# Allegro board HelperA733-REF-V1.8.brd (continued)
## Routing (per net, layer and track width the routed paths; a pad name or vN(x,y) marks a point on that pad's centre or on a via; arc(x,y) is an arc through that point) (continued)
5V-IN: length 7.6
  TOP w0.889: U1.164 57.21,41.7 57.21,42.7 U1.163
  TOP w2.032: 55.11,40.2 57.21,42.3
12V-IN: length 9.5
  TOP w0.152: R157.1 R238.2 24.4,14.4 24.47,14.33 24.47,11.77 v1(24.51,11.77)
  BOTTOM w0.152: v1(19.41,11.8) 24.45,11.8 24.47,11.77 v1(24.51,11.77)
AVCC: length 117.6
  TOP w0.152: J16.11 52.61,7.4 53.41,8.2 D58.7 D58.4 53.41,13.64 54.01,14.24 54.01,16.9 57.71,20.6 57.71,22.6 58.81,23.7 U1.182 59.21,23.7 67.41,31.9 67.41,66.83 v1(67.38,66.83) ; v1(41.01,89.2) R61.1
  BOTTOM w0.152: v1(67.38,66.83) 66.91,67.3 42.43,67.3 40.81,68.92 40.81,76.91 40.81,76.91 40.81,89 v1(41.01,89.2)
AVDD: length 47.3
  TOP w0.152: v1(140.71,77.5) 140.61,77.5 138.29,75.18 R30.1 ; v1(138.71,83.4) 138.77,83.4
  TOP w0.3: R39.2 v1(139.01,93.2)
  TOP w0.305: J4.29 143.91,58.9
  TOP w0.5: 143.91,58.9 145.61,58.9 147.11,60.4 147.11,71.1 v1(145.41,72.8)
  TOP w0.508: 140.7,87.43 140.7,84.11 140.15,83.55 138.92,83.55 D26.1
  BOTTOM w0.152: v1(139.01,93.2) v1(139.01,89.1)
  BOTTOM w0.56: v1(145.41,72.8) v1(140.71,77.5) 138.1,80.11 138.1,83.09 138.41,83.4 v1(138.71,83.4)
AVDD10: length 54.7
  TOP w0.203: U10.21 112.91,72.23 112.68,72 ; 118.06,76.33 118.03,76.3 U10.38 ; 113.71,78.62 U10.8 113.71,77.24 113.84,77.12 115.59,77.12 115.71,77.24 U10.3 115.71,78.53
  TOP w0.254: v1(121.12,79.25) 121.12,78.98 120.89,78.75 120.09,78.75 119.56,78.22 119.59,78.22 CE1.2 118.99,78.2 118.26,77.47 118.26,76.54 118.06,76.33 ; v1(116.57,80.81) 116.57,80.35 116.19,79.97 CE5.2 115.71,79.88 115.71,78.53 ; 113.71,78.62 113.71,79.78 CE4.2 ; 112.68,72 112.17,71.49 110.54,71.49 109.79,70.74 109.02,70.74 CE2.2
  TOP w0.4: L6.2 122.61,71.1 121.71,72 v1(121.41,72)
  TOP w0.5: 123.79,69.86 CE3.2 ; 123.79,69.86 CE6.2 ; 123.79,69.86 123.4,69.86 123.35,69.8 L6.2
  BOTTOM w0.3: v1(121.12,79.25) 121.12,79.17 ; 121.12,79.17 119.49,80.81 v1(116.57,80.81) 112.92,80.81 110.81,78.7 109.95,78.7 108.61,77.36 108.61,70.86 v1(108.87,70.6) ; 121.12,79.17 121.12,72.19 121.31,72 v1(121.41,72)
AVDD33: length 60.1
  TOP w0.152: 118.96,80.15 v1(118.93,80.18)
  TOP w0.203: U10.40 117.26,77.4
  TOP w0.254: v1(107.93,74.49) 107.93,74.5 108.59,74.5 RE3.1 ; RE1.1 120.44,72 v1(120.44,72.53) 120.44,73.1 R84.1 ; v1(109.31,68.58) 109.51,68.78 109.51,69.18 ; v1(112.8,68.57) 112.8,69.18 112.81,69.18 ; v1(110.09,78.01) 109.44,78.01 CE8.2 ; RE2.1 108.59,77.3 108.7,77.41 109.09,77.41 109.38,77.7 109.38,78.1 ; R85.2 108.59,82.77 108.75,82.61 109.01,82.61 109.24,82.38 FB2.2 ; 111.71,69.18 111.71,69.18 v1(111.71,68.58) ; 117.26,77.4 117.26,77.5 118.7,78.93 118.7,79.89 118.96,80.15 119.21,80.4 CE9.2 ; 116.1,72.75 116.1,71.69 116.01,71.6 115.73,71.6 115.73,72.38 115.71,72.4 U10.28 ; v1(110.51,68.58) 110.61,68.67 110.61,69.18
  TOP w0.3: 118.27,70.07 117.76,70.58 116.43,70.58 115.91,71.1 115.91,71.5 116.01,71.6 ; 118.27,70.07 CE10.2 CE12.2 ; 118.27,70.07 v1(118.85,70.07)
  BOTTOM w0.254: v1(112.8,68.57) 111.72,68.57 v1(111.71,68.58) 110.59,68.58 v1(110.51,68.58) 110.51,68.58 v1(109.31,68.58) 108.23,68.58 107.91,68.9 107.91,74.4 v1(107.93,74.49) 107.91,74.49 107.91,77.97 109.48,79.54 v1(110.09,79.54)
  BOTTOM w0.3: v1(110.09,78.01) 110.87,78.01 113.03,80.17 118.74,80.17 ; 118.74,80.17 118.75,80.18 v1(118.93,80.18) ; 118.74,80.17 119.54,80.17 120.44,79.28 120.44,72.63 120.39,72.58 v1(120.44,72.53) 119.54,72.53 118.85,71.84 v1(118.85,70.07)
  vias: v1(110.09,81.68) v1(110.09,80.96) v1(110.09,80.25) v1(110.09,80.25)
AVDD-CSI: length 26.2
  TOP w0.254: R16.1 92.05,12.93 v1(92.05,13.61) ; v1(90.53,13.61) 90.53,12.93 R15.1
  TOP w0.305: CON1.38 89.96,6.85 90.32,7.21 90.89,7.21
  TOP w0.508: 90.89,7.21 92.42,7.21 v1(92.44,7.23) ; U1.36 96.01,15.1 96.92,14.19 v1(96.92,12.94) 96.92,12.32 96.67,12.08 CP3.1 D11.2 96.62,10.66 96.92,10.36 96.92,7.31 v1(96.91,7.31)
  BOTTOM w0.254: v1(96.92,12.94) 92.71,12.94 v1(92.05,13.61) 92.05,13.61 v1(90.53,13.61)
  BOTTOM w0.508: v1(96.91,7.31) 96.91,7.23 v1(92.44,7.23)
DVDD-CSI: length 17.8
  TOP w0.305: CON1.37 89.66,3.63 90.01,3.98
  TOP w0.508: U1.35 95.01,15.14 95.01,14.4 95.31,14.1 95.31,12.36 95.03,12.08 CP2.1 D10.2 95.02,10.66 95.17,10.5 95.17,6.88 94.01,5.72 91.63,5.72 90.02,4.12 90.01,3.98
GND: length 1284.1
  TOP w0.127: v1(68.12,88.1) 68.89,87.33 UA1.41
  TOP w0.152: v1(13.21,37.6) 30.11,37.6 32.41,39.9 32.41,39.92 55.21,62.72 v1(55.21,64.8) ; v1(108.01,6.7) 108.01,6.6 106.13,8.49 106.13,11.51
  TOP w0.203: 119.24,68.4 124.83,68.4 126.23,69.8 v1(126.23,70.37) ; 119.24,68.4 118.85,68.79 v1(118.85,69.12) ; 119.24,68.4 119.24,68.34 117.79,66.89 117.34,66.89 115.65,65.19 104.67,65.19 104.04,65.19 v1(100.08,61.23) ; 44.95,80.36 44.95,77.67 46.26,76.36 46.26,76.09 ; 44.95,80.36 45.07,80.36 ; 44.95,80.36 43.18,80.36 42.4,79.58 ; 46.26,75.82 J12.45
  TOP w0.254: 19.19,26.4 19.19,26.67 ; 140.84,91.52 140.57,91.52 ; 63.93,94.28 63.66,94.28 ; 143.73,63.9 143.46,63.9 ; 85.16,6.97 85.16,6.85 ; 138.19,80.9 137.92,80.9 ; 25.11,76.75 25.11,76.48 ; 87.21,40.97 87.21,40.7 ; 28.69,81.42 28.69,81.15 ; 115.24,14.52 115.24,14.25 ; 97.71,9.17 97.71,9.44 ; 37.71,92.34 37.71,92.08 ; 75.4,99.65 75.66,99.65 ; 81.11,97.41 81.11,97.53 ; v1(43.86,92.41) 43.87,92.4 43.87,91.59 43.77,91.49 43.77,91.03 43.68,90.94 D48.1 ; 5.65,83.38 5.65,83.65 ; 97.36,86.9 97.36,87.16 ; 141.41,93.36 141.41,93.62 ; 136.39,71.38 136.39,71.65 ; 76.12,98.93 76.12,99.2 ; 37.26,74.01 37.26,74.27 ; 52.2,97.85 52.2,97.58 ; 14.58,63.12 14.31,63.12 ; 69.09,97.52 69.09,97.25 ; 76.84,99.65 76.58,99.65 ; 125.15,69.3 124.89,69.3 ; 102.46,86.79 102.73,86.79 ; 141.69,69.9 141.7,69.9 ; 75.05,87.2 74.79,87.2 ; 73.44,4.2 73.71,4.2 ; 75.48,2.93 75.21,2.93 ; 45.91,11.39 45.91,11.13 ; 137.65,78 137.65,78.27 ; 22.87,86.48 22.87,86.75 ; 34.16,72.63 34.16,72.9 ; 114.71,73.53 114.71,73.8 ; 46.53,90.94 46.26,90.94 ; 80.51,88.78 80.51,89.05 ; 146.24,16.2 146.51,16.2 ; 143.76,77.08 143.76,77.35 ; 87.21,38.43 87.21,38.7 ; 18.97,86.48 18.97,86.75 ; 11.51,76.75 11.51,76.48 ; 77.4,90.35 77.4,90.08 ; 26.59,15.28 26.86,15.28 ; 75.48,5.47 75.21,5.47 ; 18.97,87.52 18.97,87.25 ; 35.76,76.09 35.76,75.82 ; 148.78,16.2 148.51,16.2 ; 136.91,78.9 137.18,78.9 ; 27.95,80.9 27.69,80.9 ; 136.07,8.98 136.07,9.25 ; 141.69,59.4 141.71,59.4 ; 47.69,77.58 47.69,77.85 ; 75.48,4.2 75.21,4.2 ; 29.59,53.9 29.86,53.9 ; 54.22,91.17 54.22,91.44 ; 139.94,92.25 139.94,91.99 ; 144.35,82.2 144.35,82.47 ; 129.65,10.02 129.65,9.75 ; 44.64,88.3 44.65,88.29 v1(44.65,88.28) ; 136.71,80.9 136.98,80.9 ; 31.06,57.3 30.8,57.3 ; 26.31,49.64 26.31,49.91 ; 9.51,67.55 9.51,67.28 ; 49.07,91.7 49.34,91.7 ; 75.33,96.03 75.06,96.03 ; 141.41,91.14 141.41,90.88 ; 13.31,50.74 13.31,50.47 ; 79.16,94.69 79.43,94.69 ; 49.91,11.39 49.91,11.13 ; 74.46,3.4 74.46,3.13 ; 77.39,90.48 77.39,90.75 ; 61.89,94.28 62.16,94.28 ; 140.01,92.74 140.01,93.01 ; 140.91,79.16 140.91,79.43 ; 50.44,77.58 50.44,77.85 ; 88.65,87.5 88.39,87.5 ; 129.37,3.3 129.64,3.3 ; 145.09,79.1 144.82,79.1 ; 65.71,81.06 65.71,81.33 ; 68.06,93.21 68.33,93.21 ; 29.59,55.6 29.86,55.6 ; 30.33,40.4 30.33,40.67 ; 136.09,83.33 136.09,83.07 ; 62.41,93.76 62.41,94.03 ; 74.81,96.54 74.81,96.28 ; 77.39,91.52 77.39,91.25 ; 135.31,2.03 135.31,2.3 ; v1(43.2,88.21) 43.2,87.99 44.84,86.35 v1(51.44,86.35) ; 120.95,80.4 120.69,80.4 ; 129.65,8.98 129.65,9.25 ; 56.06,92.57 55.79,92.57 ; 8.37,84.42 8.37,84.15 ; 88.14,85.48 88.14,85.75 ; 1.31,63.74 1.31,63.47 ; 56.22,97.85 56.22,97.58 ; 5.65,84.42 5.65,84.15 ; 49.2,92.45 49.2,92.72 ; 77.8,3.34 78.06,3.34 ; 74.46,2.46 74.46,2.73 ; 14.24,41 13.97,41 ; 91.33,3.34 91.06,3.34 ; 1.31,50.74 1.31,50.47 ; 14.35,28.23 14.35,27.97 ; 12.04,50.12 12.31,50.12 ; 1.18,83.9 1.45,83.9 ; 76.27,100.8 76.54,100.8 ; 6.32,38.65 6.59,38.65 ; 88.67,90.5 88.4,90.5 ; 141.93,93.88 141.66,93.88 ; 52.76,76.09 52.76,75.82 ; 25.79,53.93 26.06,53.93 ; 85.94,39.7 86.21,39.7 ; 2.58,50.12 2.31,50.12 ; 115.24,13.48 115.24,13.75 ; 137.67,60.1 137.94,60.1 ; 112.94,75.3 113.21,75.3 ; 31.06,41.3 30.8,41.3 ; 84.81,94.77 84.81,94.79 ; 144.35,80 144.35,79.73 ; 123.88,9.5 124.15,9.5 ; 32.58,74.88 32.32,74.88 ; 13.64,44.52 13.64,44.4 ; 56.79,97.33 56.52,97.33 ; 108.07,80.2 108.34,80.2 ; 19.44,59.6 19.18,59.6 ; 131.25,3.3 130.99,3.3 ; 43.26,74.01 43.26,74.27 ; 8.37,83.38 8.37,83.46 ; 144.65,82 144.65,81.73 ; 96.11,9.17 96.11,9.44 ; 94.51,9.17 94.51,9.44 ; 63.93,97.03 63.66,97.03 ; 77.4,89.05 77.4,89.32 ; 31.06,46.4 30.8,46.4 ; 26.31,54.44 26.31,54.18 ; 125.15,70.3 124.89,70.3 ; 133.65,22.92 133.65,22.65 ; 37.31,61.66 37.31,61.93 ; 130.31,2.03 130.31,2.3 ; 45.13,90.94 44.86,90.94 ; 38.81,90.24 38.81,89.97 ; 138.19,76.9 137.92,76.9 ; 74.46,4.67 74.46,4.4 ; 15.11,67.55 15.11,67.28 ; 109.23,90.95 108.96,90.95 ; 143.73,60.9 143.46,60.9 ; 101.76,86.9 101.76,87.16 ; 6.32,34.65 6.59,34.65 ; 92.59,12.93 92.86,12.93 ; 78.21,2.5 78.21,2.76 ; 27.63,15.28 27.36,15.28 ; 18.31,67.55 18.31,67.28 ; 108.41,68.76 108.41,68.8 ; 108.36,91.92 108.36,91.65 ; 31.06,55.6 30.8,55.6 ; 138.19,61.62 138.19,61.35 ; 20.05,87.52 20.05,87.25 ; 40.26,76.09 40.26,75.82 ; 123.58,55.3 123.85,55.3 ; 62.41,97.54 62.41,97.28 ; 26.96,50.29 26.69,50.29 ; 22.71,76.75 22.71,76.48 ; 31.16,73.01 31.16,73.27 ; 8.94,83.9 8.67,83.9 ; 29.59,57.3 29.86,57.3 ; 51.67,26.08 51.67,26.35 ; 1.75,84.42 1.75,84.15 ; 16.05,86.48 16.05,86.75 ; 9.51,65 9.51,65.27 ; 33.29,74.27 33.56,74.27 ; 100.49,10.66 100.76,10.66 ; 125.31,2.03 125.31,2.3 ; 141.71,17.13 141.71,16.86 ; 136.64,9.5 136.37,9.5 ; 144.35,84 144.35,83.73 ; 52.76,74.01 52.76,74.1 ; 16.49,42.38 16.76,42.38 ; 116.48,75.3 116.21,75.3 ; 125.67,58.6 125.4,58.6 ; 74.46,5.94 74.46,5.67 ; 141.93,90.62 141.66,90.62 ; 137.65,79.8 137.65,79.53 ; 46.26,74.01 46.26,74.06 ; 94.51,13.44 94.51,13.18 ; 23.95,87.52 23.95,87.25 ; 108.07,78 108.34,78 ; 56.22,96.81 56.22,97.07 ; 16.05,87.52 16.05,87.25 ; 130.07,101.4 130.34,101.4 ; 53.26,76.09 53.26,75.82 ; 141.43,79.68 141.16,79.68 ; 108.07,79.1 108.34,79.1 ; 124.15,55.82 124.15,55.55 ; 22.87,87.52 22.87,87.25 ; 88.14,88.58 88.14,88.85 ; 143.61,83.1 143.88,83.1 ; 63.41,97.54 63.41,97.28 ; 88.14,88.02 88.14,87.75 ; 17.99,56.08 17.99,56.35 ; 43.26,76.09 43.26,75.82 ; 141.69,62.4 141.96,62.4 ; 36.61,90.24 36.61,89.97 ; 25.89,45.88 25.89,46.15 ; 23.74,12.88 23.74,13.1 ; 137.67,59.1 137.94,59.1 ; 65.41,93.04 65.41,92.78 ; 52.2,96.81 52.2,97.07 ; 141.69,65.4 141.96,65.4 ; 81.63,95.44 81.36,95.44 ; 88.14,86.52 88.14,86.25 ; 25.31,14.76 25.31,15.03 ; 36.61,90.37 36.61,90.64 ; 88.14,91.38 88.14,91.65 ; 131.46,88.59 131.19,88.59 ; 26.83,53.93 26.56,53.93 ; 93.11,9.17 93.11,9.44 ; 29.59,50.6 29.86,50.6 ; 51.63,97.33 51.9,97.33 ; 41.76,74.01 41.76,74.27 ; 100.66,86.9 100.66,87.16 ; 93.73,100.55 93.46,100.55 ; 8,41.15 7.74,41.15 ; 69.59,98.04 69.86,98.04 ; 26.31,45.34 26.31,45.08 ; 18.88,66.28 18.62,66.28 ; 125.31,4.57 125.31,4.3 ; 76.12,100.38 76.12,100.11 ; 94.78,90.95 94.51,90.95 ; 45.37,80.8 45.64,80.8 ; 87.84,11.39 87.84,11.13 ; 88.02,91.15 88.02,90.88 ; 1.31,49.5 1.31,49.77 ; 130.15,95.22 130.15,94.95 ; 53.91,11.39 53.91,11.13 ; 141.69,63.9 141.74,63.9 ; 62.47,88.4 62.74,88.4 ; 91.99,100.55 92.26,100.55 ; 78.09,86.5 78.36,86.5 ; 39.33,89.72 39.06,89.72 ; 11.91,67.55 11.91,67.28 ; 49.2,93.75 49.2,93.48 ; 54.86,75.92 54.86,75.65 ; 88.02,85.15 88.02,84.88 ; 90.91,9.37 90.91,9.41 ; 139.05,94.1 138.79,94.1 ; 41.76,76.09 41.76,75.82 ; 93.76,89.93 93.76,90.2 ; 133.59,78.47 133.86,78.47 ; 79.76,5.23 79.76,5.5 ; 31.06,44.7 30.8,44.7 ; 80.59,95.44 80.86,95.44 ; 24.51,23.38 24.25,23.38 ; 138.39,78.9 138.12,78.9 ; 130.59,100.88 130.59,101.15 ; 34.16,75.92 34.16,75.65 ; 46.01,90.37 46.01,90.64 ; 29.74,74.88 30,74.88 ; 26.74,55.28 26.74,55.55 ; 62.47,87.3 62.74,87.3 ; 143.91,81.1 144.18,81.1 ; 124.64,68.78 124.64,69.05 ; 48.55,93.1 48.82,93.1 ; 113.51,81.76 113.51,81.49 ; 144.28,77.6 144.01,77.6 ; 82.69,95.34 82.96,95.34 ; 1.75,83.38 1.75,83.65 ; 147.51,15.26 147.51,15.53 ; 144.65,80.2 144.65,80.47 ; 126.25,3.3 125.99,3.3 ; 49.59,88.78 49.59,89.05 ; 13.31,62.5 13.31,62.77 ; 141.69,66.9 141.71,66.9 ; 88.65,91.9 88.39,91.9 ; 75.49,95.18 75.76,95.18 ; 136.71,76.9 136.98,76.9 ; 138.54,94.62 138.54,94.35 ; 137.58,69.83 137.61,69.83 ; 134.37,3.3 134.64,3.3 ; 93.11,13.44 93.11,13.18 ; 61.89,97.03 62.16,97.03 ; 129.08,9.5 129.35,9.5 ; 49.26,76.09 49.26,75.82 ; 92.74,90.95 93.01,90.95 ; 35.81,62.32 35.81,62.05 ; 8.31,76.75 8.31,76.48 ; 88.67,84.5 88.4,84.5 ; 31.06,53.9 30.8,53.9 ; 75.05,88.2 74.79,88.2 ; 86.31,43.97 86.31,43.7 ; 21.75,18.7 21.49,18.7 ; 86.31,41.43 86.31,41.7 ; 135.87,71.9 136.14,71.9 ; 13.83,27.72 14.1,27.72 ; 137.45,80 137.45,80.27 ; 62.6,84.65 62.6,84.38 ; 88.65,86 88.39,86 ; 125.64,63.3 125.38,63.3 ; 31.06,52.3 30.8,52.3 ; 30.33,58.2 30.33,57.94 ; 1.86,76.74 1.86,76.48 ; 124.45,8.98 124.45,9.25 ; 124.37,3.3 124.64,3.3 ; 138.04,91.86 138.04,91.59 ; 53.61,86.56 53.61,86.83 ; 20.05,86.48 20.05,86.75 ; 53.09,87.08 53.36,87.08 ; 52.24,26.6 51.97,26.6 ; 34.41,88.36 34.41,88.62 ; 1.86,73.01 1.86,73.27 ; 17.01,41.86 17.01,42.12 ; 130.31,4.57 130.31,4.3 ; 66.41,93.04 66.41,92.78 ; 144.35,78.2 144.35,78.47 ; 145.39,81.1 145.12,81.1 ; 54.86,72.63 54.86,72.9 ; 57.91,11.39 57.91,11.13 ; 25.37,46.4 25.64,46.4 ; 40.26,74.01 40.26,74.27 ; 76.79,101.32 76.79,101.05 ; 31.16,76.74 31.16,76.48 ; 35.26,74.01 35.26,74.27 ; 31.06,50.6 30.8,50.6 ; 88.14,89.62 88.14,89.35 ; 107.49,100.55 107.76,100.55 ; 92.59,9.74 92.86,9.74 ; 1.31,62.5 1.31,62.77 ; 13.31,63.74 13.31,63.47 ; 38.76,76.09 38.76,75.82 ; 139.03,91.52 139.3,91.52 ; 45.49,90.94 45.76,90.94 ; 25.79,44.83 26.06,44.83 ; 88.02,89.85 88.02,90.12 ; 103.11,86.14 103.11,86.41 ; 88.65,89.1 88.39,89.1 ; 135.36,82.61 135.63,82.61 ; 88.02,83.85 88.02,84.12 ; 87.58,42.7 87.31,42.7 ; 17.11,76.75 17.11,76.48 ; 135.31,4.57 135.31,4.3 ; 92.86,99.18 92.86,99.45 ; 32.79,88.88 33.06,88.88 ; 80.46,94.69 80.19,94.69 ; 49.59,91.18 49.59,91.45 ; 33.31,88.36 33.31,88.62 ; 19.93,27.3 19.66,27.3 ; 27.11,67.55 27.11,67.28 ; 130.81,87.94 130.81,88.21 ; 21.05,11.78 21.05,11.51 ; 54.13,87.08 53.86,87.08 ; 35.26,76.09 35.26,75.82 ; 123.48,66.7 123.75,66.7 ; 46.26,76.09 46.26,75.82 ; 137.39,91.21 137.66,91.21 ; 25.81,50.29 25.93,50.29 ; 18.46,27.3 18.72,27.3 ; 63.41,93.76 63.41,94.03 ; 131.46,96.69 131.19,96.69 ; 37.26,76.09 37.26,75.82 ; 137.67,58.1 137.94,58.1 ; 138.68,91.21 138.42,91.21 ; 4.57,84.42 4.57,84.15 ; 138.15,65.88 138.15,66.15 ; 137.58,66.4 137.85,66.4 ; 30.33,49.7 30.33,49.97 ; 93.76,91.97 93.76,91.7 ; 36.71,61.58 36.45,61.58 ; 17.47,56.6 17.74,56.6 ; 73.33,98.04 73.06,98.04 ; 108.36,99.18 108.36,99.45 ; 49.59,92.22 49.59,91.95 ; 87.26,2.03 87.26,2.08 ; 38.76,74.01 38.76,74.27 ; 108.36,101.92 108.36,101.65 ; 101.01,11.23 101.01,10.96 ; 23.95,86.48 23.95,86.75 ; 130.16,96.69 130.43,96.69 ; 112.86,81.11 113.13,81.11 ; 35.76,74.01 35.76,74.27 ; 145.09,83.1 144.82,83.1 ; 92.86,101.92 92.86,101.65 ; 52.38,92.57 52.64,92.57 ; 35.81,60.85 35.81,61.11 ; 14.11,79.98 14.11,80.25 ; 81.94,11.39 81.94,11.13 ; 53.76,76.09 53.76,75.82 ; 27.44,81.42 27.44,81.15 ; 140.66,93.39 140.39,93.39 ; 17.47,57.6 17.74,57.6 ; 21.56,11.26 21.3,11.26 ; 124.03,64.88 124.03,65.14 ; 147.51,17.14 147.51,16.88 ; 81.11,94.87 81.11,95.14 ; 23.03,27.73 22.76,27.73 ; 73.44,2.93 73.71,2.93 ; 140.39,79.68 140.66,79.68 ; 137.45,77.8 137.45,77.53 ; 17.53,42.38 17.26,42.38 ; 29.59,52.3 29.86,52.3 ; 96.11,13.44 96.11,13.18 ; 26.83,44.83 26.56,44.83 ; 54.22,93.96 54.22,93.7 ; 137.67,61.1 137.94,61.1 ; 12.04,63.12 12.31,63.12 ; 88.48,39.7 88.21,39.7 ; 79.81,94.04 79.81,94.31 ; 115.75,14 115.49,14 ; 46,25.18 46,24.91 ; 97.58,75.7 97.31,75.7 ; 22.71,23.38 22.98,23.38 ; 113.91,68.66 113.91,68.93 ; 38.31,61.66 38.31,61.93 ; 15.48,87 15.75,87 ; 139.94,90.78 139.94,91.05 ; 73.44,5.47 73.71,5.47 ; 51.51,77.56 51.51,77.83 ; 140.89,90.62 141.16,90.62 ; 109.23,100.55 108.96,100.55 ; 108.36,89.98 108.36,90.25 ; 98.46,86.9 98.46,87.16 ; 85.04,42.7 85.31,42.7 ; 55.73,74.27 55.46,74.27 ; 107.89,69.28 108.16,69.28 ; 136.81,82.61 136.55,82.61 ; 134.11,77.96 134.11,78.22 ; 84.88,11.42 84.88,11.15 ; 130.81,96.04 130.81,96.31 ; 74.46,3.73 74.46,4 ; 136.55,10.6 136.29,10.6 ; 27.11,14.76 27.11,15.03 ; 108.07,75.8 108.34,75.8 ; 49.07,89.3 49.34,89.3 ; 103.76,86.79 103.49,86.79 ; 28.17,80.9 28.44,80.9 ; 136.25,3.3 135.99,3.3 ; 74.46,5 74.46,5.27 ; 39.91,90.37 39.91,90.64 ; 22.14,75.47 22.41,75.47 ; 2.58,63.12 2.31,63.12 ; 88.14,86.98 88.14,87.25 ; 46,23.73 46,24
  TOP w0.3: J4.19 141.74,63.9 v1(141.62,63.88) ; J12.73 53.26,73.82 53.21,73.82 v1(53.21,71.4) ; v1(70.44,92.29) 70.44,92.7 69.94,93.21 CA1.1 ; U14.5 140.21,31.6 v1(140.21,31.6) ; CON1.41 78.21,4.25 v1(78.06,4.4) ; 82.46,1.82 CON1.13 ; 82.46,1.82 84.26,1.82 ; 82.46,1.82 80.66,1.82 ; v1(68.81,79.8) 68.59,79.58 63.78,79.58 v1(62.35,81.01) 55.17,81.01 51.84,84.34 44.43,84.34 43.23,83.14 39.25,83.14 38.51,82.4 34.01,82.4 31.04,79.43 17.86,79.43 16.81,80.48 16.81,81.1 ; D15.1 9.21,41 v1(8.81,40.6) 8.81,40.1 ; 88.18,91.94 87.67,92.45 86.36,92.45 v1(86.01,92.1) ; 88.18,91.94 88.14,91.94 C64.2 ; 88.18,91.94 C64.2 ; 88.18,91.94 89.21,92.97 v1(89.21,93.4) v1(89.21,95.8) 89.21,96.6 88.58,97.24 v1(87.51,97.24) ; CON2.19 7.91,40.15 7.96,40.1 8.81,40.1 ; v1(67.41,93.09) 67.41,92.53 ; 67.41,92.53 RA26.2 ; 67.41,92.53 RA4.2 CA14.2 ; v1(57.81,7.6) 57.91,7.6 D57.8 D57.3 ; U44.6 20.96,12.36 v1(20.99,12.47) 20.99,12.39 ; v1(103.81,9.2) 103.81,7.54 105.91,5.44 105.91,4.19 104.92,3.19 v1(104.91,3.2) ; v1(11.71,33.1) 11.76,33.15 CON2.5 ; v1(21.21,17.9) 21.24,17.93 C3.2 ; C94.2 25.22,49.2 23.38,49.2 22.96,48.78 22.96,48.75 v1(22.61,48.4) ; 22.51,27.73 22.51,28.94 v1(23.41,29.84) ; J12.45 46.26,74.06 v1(46.26,73.6) ; 137.23,74.82 137.04,75.02 C35.2 ; 137.23,74.82 v1(137.42,75) ; 137.23,74.82 137.89,74.16 137.89,74.15 138.27,73.78 138.29,73.78 R36.2 ; v1(62.63,84.73) 62.63,84 CA18.2 ; J12.71 52.76,74.1 52.41,73.75 v1(52.41,71.6) ; CB8.1 50.46,78.08 R333.2 R235.2 ; v1(45.89,81.76) CB9.1 ; v1(13.21,37.6) C27.2 ; C27.2 12.32,38.22 C26.1 ; C27.2 11.8,37.08 11.8,36.59 11.36,36.15 CON2.11 ; 57.47,89.77 57.47,88.02 57.81,87.68 v1(57.81,84.97) ; 57.47,89.77 v1(57.47,89.82) ; 57.47,89.77 v1(57.47,90.79) ; CON3.18 v1(18.31,64.4) ; RL2.1 v1(14.51,44) ; RL2.1 13.64,44.4 13.61,44.4 13.41,44.6 10.81,44.6 10.65,44.44 D18.1 ; RL2.1 CL1.2 ; 86.66,1.82 87,1.82 87.26,2.08 CON1.29 87.26,4.12 v1(87.28,4.12) ; 86.66,1.82 CON1.27 ; 86.66,1.82 86.06,1.82 ; D28.2 135.19,73.8 v1(135.19,73.82) ; v1(131.21,27.7) 130.92,27.7 130.51,28.11 105.85,28.11 100.08,22.34 v1(100.03,22.34) ; RE4.1 CE9.1 C62.1 ; v1(81.98,8.41) 83.36,7.02 CON1.16 ; v1(140.24,33.08) 140.22,33.1 U14.2 ; CU1.1 28.11,85.6 ; 28.11,85.6 28.02,85.69 CU2.1 v1(28.01,87.9) ; 28.11,85.6 CU3.1 ; D59.3 D59.8 49.91,8.27 49.29,7.65 v1(49.29,7.58) ; D55.3 40.86,17.03 40.86,16.17 D55.8 v1(40.91,13.3) 40.86,13.25 40.86,12.6 40.71,12.3 37.81,12.3 36.61,11.1 36.61,4 37.32,3.29 J14.4 ; CA13.2 65.81,81.58 65.81,81.47 v1(66.22,81.01) ; 113.91,69.18 113.97,69.18 v1(113.97,68.58) ; v1(73.28,91.88) 73.2,91.88 73.13,91.81 73.13,93.85 72.91,94.07 v1(72.91,94.5) CA5.1 ; v1(83.43,8.29) 83.73,8.29 85.16,6.85 CON1.22 ; CON2.2 10.96,31.65 v1(11.71,30.9) 12.22,30.9 12.32,30.8 27.91,30.8 v1(57.71,60.6) ; v1(143.87,65.32) 143.74,65.4 J4.16 ; 26.61,40.1 30.44,40.1 31.21,40.87 31.21,40.9 49.91,59.6 v1(49.91,59.9) v1(49.91,60.8) 49.91,61.46 50.04,61.58 CB3.1 50.83,62.2 51.51,62.2 51.51,62.18 ; 26.61,40.1 26.32,40.1 26.31,40.09 ; 26.61,40.1 26.31,40.4 ; v1(7.71,62.6) 8.51,63.49 9.41,64.39 9.41,66.28 CON3.40 ; v1(78.98,8.44) 79.76,7.66 CON1.4 ; CE3.1 124.64,71.48 123.97,72.14 v1(123.18,72.14) ; CE5.1 115.81,81.12 116.3,81.61 v1(116.53,81.61) ; v1(47.71,77.3) 47.71,77.89 47.69,77.91 R334.2 R234.2 ; J4.22 143.79,62.4 v1(143.86,62.38) ; v1(13.91,73.9) CON3.29 13.91,77.3 14.11,77.5 33.01,77.5 34.91,79.4 v1(36.21,79.4) 36.39,79.58 42.4,79.58 42.78,79.2 42.78,77.72 44.23,76.27 44.55,76.27 44.76,76.07 44.76,73.78 v1(44.38,73.4) ; C33.1 v1(135.71,72.8) ; v1(61.06,76.78) 60.82,76.77 60.05,76 55.05,76 v1(54.71,76.34) v1(52.99,78.06) 52.99,78.52 v1(51.81,79.7) ; R83.1 120.59,74.36 121.5,74.36 ; CON2.15 9.16,38.15 v1(9.31,38.3) 8.96,38.65 CON2.16 ; R41.1 130.19,94.83 130.01,95 130.26,95.25 v1(130.21,95.3) ; v1(26.21,15.2) 26.14,15.28 R6.1 24.74,15.28 24.51,15.5 v1(24.51,16.3) 23.74,16.3 R158.2 ; v1(4.41,83.2) 4.46,83.15 4.57,83.26 D78.2 ; v1(25.11,46.4) v1(25.11,45.2) ; 16.71,17.1 R156.2 16.71,17 17.41,16.3 ; CON2.18 8.56,39.65 8.81,39.9 8.81,40.1 ; v1(10.71,73.9) CON3.37 v1(10.71,77.4) ; 131.47,67.2 J3.31 J3.32 ; v1(22.49,55.89) 22.49,56.58 22.51,56.6 v1(22.56,56.76) ; CON3.35 v1(11.51,73.9) ; J21.5 15.13,55.1 15.82,55.8 16.04,55.8 16.99,56.74 16.99,57.32 17.86,58.19 22.61,58.19 27.11,62.69 v1(27.11,64.4) CON3.4 ; v1(16.51,59.9) 16.81,59.6 D72.8 17.98,59.65 18.84,59.65 D72.3 ; v1(134.44,92.8) 134.34,92.9 130.49,92.9 130.13,92.54 130.13,89.27 C38.2 ; C20.1 76.01,94.4 74.91,93.3 v1(74.81,93.3) ; v1(141.57,69.85) 141.7,69.9 J4.7 ; 13.67,40.1 R20.1 ; 13.67,40.1 v1(14.51,40.1) ; 13.67,40.1 D17.1 ; 84.26,1.82 86.06,1.82 ; 84.26,1.82 CON1.19 ; 86.06,1.82 CON1.25 ; v1(85.81,97.2) 86.64,97.2 86.68,97.24 v1(87.51,97.24) ; J4.28 141.71,59.4 141.58,59.38 v1(140.51,59.4) ; v1(15.11,64.5) CON3.26 ; v1(24.61,83.26) C84.2 ; v1(24.61,83.26) 24.77,83.1 U13.2 v1(27.92,83.1) 27.92,82.11 v1(27.91,82.1) ; v1(24.61,83.26) 24.61,83.4 24.41,83.6 24.41,84.1 v1(24.11,84.4) 24.01,84.5 v1(22.91,84.5) ; v1(107.27,68.84) 107.51,68.6 108.21,68.6 108.41,68.8 CE2.1 ; CP4.2 v1(97.71,13.8) ; v1(137.71,65.6) 135.3,65.6 134.98,65.28 134.98,62.18 135.69,61.48 136.41,61.48 v1(136.68,61.74) ; 22.81,84.5 22.91,84.6 v1(22.91,84.5) ; 22.81,84.5 v1(22.91,84.5) ; 22.81,84.5 v1(21.61,84.5) v1(20.31,84.5) ; C13.2 26.31,40.4 ; 26.31,40.4 26.31,40.09 ; v1(33.42,78.23) 35.46,80.27 40.92,80.27 41.43,80.78 43.99,80.78 45.61,82.4 50.98,82.4 54.65,78.73 61.32,78.73 62.43,77.62 65.48,77.62 66,77.1 v1(67.41,77.1) ; v1(63.38,93.55) 62.09,93.55 60.51,91.97 60.51,84.45 58.65,82.6 55.36,82.6 53.23,84.73 v1(53.23,85.63) ; v1(21.71,11.07) 21.71,9.2 v1(21.61,9.1) ; v1(13.51,17.1) v1(14.61,17.1) 15.11,17.6 17.21,17.6 17.41,17.4 17.41,16.3 ; CON2.8 11.76,34.65 v1(11.71,34.6) ; v1(58.91,13.9) 58.31,14.5 58.31,17.2 58.81,17.7 U1.188 ; v1(90.69,9.01) 90.69,9.19 90.91,9.41 D8.8 D8.3 ; v1(2.21,83) 2.55,82.66 2.55,82.27 3.83,81 10.31,81 v1(11.21,81.9) ; C64.2 88.31,91.9 ; U14.17 136.31,25.6 v1(136.21,25.7) ; U14.8 140.18,30.1 v1(140.21,30.07) ; J12.57 49.26,75.1 49.28,75.1 v1(49.28,76.18) ; v1(141.31,66.5) 141.71,66.9 J4.13 ; v1(18.91,49.2) 18.77,49.2 18.77,50.28 C90.2 ; D58.3 D58.8 53.91,7.8 v1(53.81,7.7) ; U2.2 v1(15.45,25.99) ; R239.1 23.74,13.1 23.75,13.09 v1(23.75,10.63) ; R34.2 138.21,56.06 ; 138.21,56.06 R35.2 ; 138.21,56.06 v1(137.59,56.06) ; 26.31,40.09 v1(26.22,40) ; 17.41,16.3 17.41,15.6 v1(18.11,14.9) ; v1(140.21,28.6) 140.21,28.6 U14.11 ; CON2.21 5.71,41.15 5.61,41.05 v1(5.61,40.6) 5.66,40.65 CON2.20 ; 16.95,41.66 v1(16.91,41.7) ; D61.2 84.81,94.79 84.31,94.29 v1(84.31,93.8) ; v1(117.26,25.96) 126.01,25.96 126.05,26 v1(126.71,26) ; v1(14.71,73.9) CON3.27 ; v1(47.73,73.56) 47.76,73.56 v1(47.76,76.44) ; v1(35.04,83.87) 35.37,83.55 38.18,83.55 v1(38.41,83.77) ; v1(133.61,24.4) R92.2 ; v1(60.81,14.6) 60.21,14.6 59.71,15.1 59.71,16.3 60.31,16.9 v1(60.41,17.3) ; v1(130.21,96) 130.58,96.46 130.58,96.69 C44.2 ; v1(63.01,100.8) 63.01,99.32 63.44,98.89 65.92,98.89 66.41,99.38 v1(66.41,99.7) 66.56,99.85 v1(70.12,99.85) ; v1(140.51,60.8) 141.59,60.9 141.59,60.9 J4.25 ; J4.30 141.69,58.4 141.56,58.44 v1(140.51,58.5) ; J4.10 141.67,68.4 v1(141.61,68.42) ; 22.78,20.1 22.88,20.2 ; v1(136.01,10) 136.01,9.5 D41.1 ; v1(17.11,73.9) CON3.21 ; D82.2 124.15,52.86 v1(124.51,52.5) ; 71.95,91.89 71.95,93.13 v1(71.03,94.05) 71.02,94.04 69.95,95.11 69.94,95.11 RA12.2 ; 71.95,91.89 v1(71.95,89.51) ; 71.95,91.89 71.98,91.86 71.98,91.86 v1(71.95,91.86) ; CA3.1 RA2.1 CA2.2 CA10.2 ; v1(116.94,68.54) 116.94,68.9 117.21,69.18 ; CE1.1 121.51,78.2 CE14.1 ; v1(22.71,73.9) CON3.15 ; v1(8.01,73.9) 8.16,73.9 8.16,75.47 CON3.43 ; D60.3 D60.8 45.91,8.9 45.11,8.1 v1(45.11,7.12) ; v1(25.11,73.9) CON3.9 ; CON3.34 v1(11.91,64.5) ; D76.2 8.37,83.46 v1(8.11,83.2) ; C42.2 140.01,93.4 140.49,93.88 C43.2 141.31,93.78 v1(141.31,93) ; 131.51,67.2 v1(132.39,68.08) ; v1(134.57,66.69) 135.78,67.9 D80.2 ; D23.2 130.51,102.4 v1(130.51,101.9) ; v1(87.51,97.24) J19.A1 ; v1(13.65,23.59) v1(14.45,23.59) ; v1(131.71,26.5) 132.41,26.5 132.51,26.4 U16.3 ; v1(39.21,61.4) 39.21,62.18 ; v1(79.81,97.3) 80.88,97.3 81.11,97.53 J19.B1 ; v1(145.76,43.59) 144.75,43.59 143.54,44.8 J5.3 v1(139.41,44.8) ; v1(80.51,8.45) 81.56,7.4 CON1.10 ; CON1.1 78.86,1.98 79.03,1.82 80.66,1.82 ; 80.66,1.82 CON1.7 ; C86.2 21.04,80.42 v1(21.67,80.42) 21.69,80.4 C87.2 ; 118.31,69.18 119.41,69.18 ; v1(59.02,90) 59.02,84.49 58.2,83.66 56.28,83.66 55.5,84.45 v1(55.5,88.55) ; J12.75 53.76,72.2 v1(53.81,72.2)
  TOP w0.381: 125.12,101.09 124.85,101.09 ; 32.21,2.26 32.21,2.53 ; 145.23,20.83 145.23,21.1 ; 10.91,8.23 10.91,8.5 ; 15.89,96.3 15.63,96.3 ; 79.22,99.57 79.49,99.57 ; 14.61,94.13 14.61,94.4 ; 51.61,78.1 51.51,78.1 51.61,78 51.61,77.7 v1(51.31,77.4) 50.84,76.93 50.84,73.64 50.06,72.86 47.34,72.86 47.01,73.2 v1(47.01,73.77) ; 79.99,100.89 79.99,100.62 ; 113.04,89.84 113.31,89.84 ; 7.71,12.03 7.71,12.3 ; 115.1,89.84 114.83,89.84 ; 18.11,92.77 18.11,93.04 ; 143.66,21.85 143.92,21.85 ; 145.24,35.34 145.24,35.61 ; 19.14,90.8 18.87,90.8 ; 89.4,103.75 89.13,103.75 ; 131.47,67.2 131.74,67.2 ; 146.78,95.88 146.78,95.61 ; 8.58,13.8 8.31,13.8 ; 14.61,88.63 14.61,88.9 ; 88.63,100.89 88.63,100.62 ; 114.07,90.87 114.07,90.6 ; 62.61,2.33 62.61,2.6 ; 13.33,96.3 13.59,96.3 ; 31.18,3.29 31.45,3.29 ; 124.09,100.06 124.09,100.33 ; 14.61,98.47 14.61,98.21 ; 137.35,36.35 137.62,36.35 ; 33.24,3.29 32.97,3.29 ; 19.14,93.8 18.87,93.8 ; 123.06,101.09 123.33,101.09 ; 50.01,21.83 50.01,22.09 ; 59.74,3.2 60.01,3.2 ; 13.33,90.8 13.59,90.8 ; 12.68,9.1 12.41,9.1 ; 61.48,3.2 61.21,3.2 ; 63.48,3.2 63.21,3.2 ; 144.72,93.81 144.98,93.81 ; 61.74,3.2 62.01,3.2 ; 146.82,36.36 146.55,36.36 ; 124.09,102.12 124.09,101.85 ; 9.14,9.1 9.41,9.1 ; 18.11,94.83 18.11,94.56 ; 6.84,13.8 7.11,13.8 ; 139.27,37.37 139.27,37.1 ; 27.33,90.8 27.59,90.8 ; 79.22,103.75 79.49,103.75 ; 14.61,92.97 14.61,92.71 ; 32.21,4.32 32.21,4.05 ; 79.99,102.68 79.99,102.95 ; 7.71,15.57 7.71,15.3 ; 114.07,88.81 114.07,89.08 ; 88.63,102.58 88.63,102.85 ; 143.67,36.36 143.93,36.36 ; 146.78,91.74 146.78,92.01 ; 18.11,89.77 18.11,90.04 ; 27.33,96.3 27.59,96.3 ; 137.35,21.85 137.62,21.85 ; 87.86,103.75 88.13,103.75 ; 139.27,35.33 139.27,35.6 ; 145.23,22.87 145.23,22.6 ; 148.85,93.81 148.58,93.81 ; 145.24,37.38 145.24,37.11 ; 60.61,2.33 60.61,2.6 ; 18.11,91.83 18.11,91.56 ; 60.61,4.07 60.61,3.8 ; 62.61,4.07 62.61,3.8 ; 89.4,99.57 89.13,99.57 ; 80.76,103.75 80.49,103.75 ; 10.91,9.97 10.91,9.7 ; 141.19,21.85 140.92,21.85 ; 141.19,36.35 140.92,36.35 ; 139.27,22.87 139.27,22.6
  TOP w0.4: v1(20.98,14.65) 20.95,14.67 v1(19.86,14.67)
  TOP w0.406: v1(137.61,69.83) 137.61,69.83 D13.3 D13.8 ; D7.3 87.84,10.72 87.84,10.73 v1(87.84,11.47) ; D3.3 D3.8 78.94,11.44 v1(78.95,11.46) ; v1(105.57,89.13) 105.66,89.13 D38.8 D38.3 ; D19.3 D19.8 122.96,63.3 v1(122.95,63.31) ; D20.8 D20.3 138.71,43.03 v1(138.62,43.13) ; U16.3 U16.8 135.31,26.4 v1(135.31,26.5) ; v1(132.46,32.38) 132.48,32.4 DE1.3 DE1.8 v1(135.46,32.4) ; v1(135.56,29.4) U15.8 U15.3 132.46,29.4 v1(132.45,29.39) ; D16.3 D16.8 123.44,58.6 v1(123.42,58.57) ; v1(81.94,11.5) 81.94,10.74 81.94,10.74 D5.3 ; v1(139.79,63.63) D21.8 D21.3 ; v1(84.89,11.53) 84.89,10.77 84.88,10.76 D6.3 ; v1(75.9,11.49) 75.94,11.45 D4.8 D4.3
  TOP w0.5: v1(15.45,23.59) U2.2 ; v1(21.79,13.5) U44.6 20.96,14.65 v1(20.98,14.65) 20.98,14.64 21.79,14.64 v1(21.79,14.64) ; 20.96,12.39 v1(20.99,12.47) ; v1(21.73,12.49) 21.83,12.39 20.99,12.39 ; v1(22.56,56.76) 22.61,56.7 22.71,56.6 U43.2 ; v1(27.11,50.3) 25.82,50.3 25.81,50.29 25.52,50.29 ; v1(137.11,100.6) U7.2 ; 16.71,17.1 v1(15.51,17.1)
  TOP w0.508: U1.95 99.23,75.7 v1(99.42,75.68) ; v1(134.44,100.6) 134.44,100.09 ; v1(134.44,100.6) 134.95,100.6 ; v1(134.44,100.6) 134.44,101.11 ; 134.44,100.09 134.95,100.6 ; 134.44,100.09 v1(134.44,99.58) ; X1.4 124.66,78.71 ; 124.66,78.71 125.28,78.71 125.67,78.32 125.67,74.33 125.36,74.02 121.84,74.02 121.5,74.36 121.51,74.68 ; 124.66,78.71 121.79,78.71 121.5,78.42 CE14.1 ; 134.44,101.11 v1(134.44,101.62) ; 134.44,101.11 134.95,100.6 ; U7.2 134.95,100.6 ; X1.2 122.89,75.13 v1(122.89,74.02) ; v1(53.63,92.63) 53.63,93.26 53.58,93.3 U8.7 ; v1(101.04,17.7) U1.38
  TOP w0.6: C5.2 23.61,22.1 v1(24.01,21.7) 24.11,21.6 ; v1(19.21,29) 19.19,28.98 C6.2 ; v1(31.82,43) C97.2 ; 22.78,20.1 C2.2 ; 22.88,20.2 v1(24.01,20.2) ; v1(134.44,92.8) U6.2 v1(136.71,92.8) ; 22.61,47.5 v1(22.61,47) ; 22.61,47.5 v1(22.61,47.7) ; 22.61,47.5 U3.2 v1(25.11,47.5)
  TOP w0.7: v1(18.51,7.5) 18.51,8.6 18.53,8.62 C324.2
  TOP w0.711: J7.6 v1(103.86,91.67)
  TOP w0.8: C9.2 18.41,41.23 17.38,41.23 16.95,41.66
  TOP w1.016: J3.7 J3.8 127.14,43.2 127.04,43.11 v1(126.23,43.11) ; J3.16 J3.15 ; v1(126.28,41.75) 126.84,41.2 J3.6 J3.5
  BOTTOM w0.254: 45.34,79.98 45.34,79.47 45.62,79.18 49.31,79.18 56.21,72.28 67.55,72.28 67.75,72.08 67.75,71.53 ; v1(54.71,76.34) 57.67,73.38 68.25,73.38 69.92,75.04 71.1,75.04 71.42,74.71
  BOTTOM w0.3: v1(25.11,47.5) v1(25.11,46.4) ; v1(19.01,14.9) v1(18.11,14.9) ; v1(15.45,25.99) v1(16.35,25.99) ; 45.54,80.7 45.34,80.5 45.34,79.98 ; 45.54,80.7 44.94,81.3 43.83,81.3 42.83,80.3 42.83,79.56 44.19,78.2 48.81,78.2 56.52,70.48 66.5,70.48 67.55,71.53 67.75,71.53 68.47,70.82 69.56,70.82 71.45,72.7 71.45,74.69 71.42,74.71 ; 45.54,80.7 46.07,81.23 49.33,81.23 50.93,79.64 51.42,79.64 v1(51.81,79.7) 51.43,79.61 v1(52.99,78.06) v1(54.71,76.34) ; v1(13.91,73.9) v1(14.71,73.9) ; v1(100.21,17.7) 100.21,18.7 99.21,19.7 93.81,19.7 92.81,20.7 89.24,20.7 v1(89.18,20.63) 89.18,21.46 90.19,22.48 93.5,22.48 v1(93.91,22.07) ; v1(74.21,101) 74.21,101.64 73.14,102.7 62.41,102.7 v1(61.61,101.9) ; v1(134.44,92.8) 134.44,91.83 v1(134.41,91.8) ; v1(25.11,45.2) 25.51,45.6 v1(26.31,45.6) ; v1(14.45,23.59) v1(15.45,23.59) ; v1(28.01,87.9) 28.01,86.33 27.92,86.24 v1(27.92,84.46) v1(27.92,83.1) ; v1(55.11,102.1) v1(53.01,102.1) ; v1(51.81,69.2) 53.01,69.2 v1(53.24,68.86) 53.05,69.2 53.72,68.53 55.04,68.53 55.92,69.41 55.92,70.13 v1(54.37,71.68) ; v1(11.71,30.9) v1(11.71,33.1) ; v1(139.79,63.63) 139.11,64.31 139.11,74.4 v1(137.81,75.7) ; v1(69.09,88.08) 69.07,88.1 v1(68.12,88.1) ; 126.32,43.2 v1(126.23,43.11) ; v1(18.01,49.2) v1(18.91,49.2)
  BOTTOM w0.381: 32.21,4.32 32.21,4.05 ; 87.86,99.57 88.13,99.57 ; 18.11,92.77 18.11,93.04 ; 79.22,99.57 79.49,99.57 ; 18.11,91.83 18.11,91.56 ; 29.89,96.3 29.63,96.3 ; 12.68,9.1 12.41,9.1 ; 139.27,20.83 139.27,21.1 ; 145.23,22.87 145.23,22.6 ; 60.61,4.07 60.61,3.8 ; 14.61,88.63 14.61,88.9 ; 8.58,13.8 8.31,13.8 ; 18.11,89.77 18.11,90.04 ; 143.67,36.36 143.93,36.36 ; 10.91,9.97 10.91,9.7 ; 61.48,3.2 61.21,3.2 ; 13.33,96.3 13.59,96.3 ; 33.24,3.29 32.97,3.29 ; 137.35,36.35 137.62,36.35 ; 9.14,9.1 9.41,9.1 ; 18.11,94.83 18.11,94.56 ; 113.04,89.84 113.31,89.84 ; 28.61,88.63 28.61,88.9 ; 7.71,12.03 7.71,12.3 ; 32.21,2.26 32.21,2.53 ; 139.27,37.37 139.27,37.1 ; 80.76,99.57 80.49,99.57 ; 146.78,95.88 146.78,95.61 ; 28.61,94.13 28.61,94.4 ; 19.14,90.8 18.87,90.8 ; 114.07,88.81 114.07,89.08 ; 146.81,21.85 146.54,21.85 ; 89.4,99.57 89.13,99.57 ; 60.61,2.33 60.61,2.6 ; 141.19,21.85 140.92,21.85 ; 27.33,96.3 27.59,96.3 ; 137.35,21.85 137.62,21.85 ; 19.14,93.8 18.87,93.8 ; 145.24,37.38 145.24,37.11 ; 15.89,96.3 15.63,96.3 ; 148.85,93.81 148.58,93.81 ; 29.89,90.8 29.63,90.8 ; 79.22,103.75 79.49,103.75 ; 144.72,93.81 144.98,93.81 ; 10.91,8.23 10.91,8.5 ; 15.89,90.8 15.63,90.8 ; 6.84,13.8 7.11,13.8 ; 115.1,89.84 114.83,89.84 ; 62.61,4.07 62.61,3.8 ; 139.27,35.33 139.27,35.6 ; 61.74,3.2 62.01,3.2 ; 139.27,22.87 139.27,22.6 ; 63.48,3.2 63.21,3.2 ; 27.33,90.8 27.59,90.8 ; 62.61,2.33 62.61,2.6 ; 87.86,103.75 88.13,103.75 ; 143.66,21.85 143.92,21.85 ; 7.71,15.57 7.71,15.3 ; 141.19,36.35 140.92,36.35 ; 80.76,103.75 80.49,103.75 ; 145.23,20.83 145.23,21.1 ; 13.33,90.8 13.59,90.8 ; 146.78,91.74 146.78,92.01 ; 14.61,98.47 14.61,98.21 ; 145.24,35.34 145.24,35.61 ; 31.18,3.29 31.45,3.29 ; 17.08,93.8 17.35,93.8 ; 28.61,98.47 28.61,98.21 ; 17.08,90.8 17.35,90.8 ; 51.04,22.48 50.77,22.48 ; 114.07,90.87 114.07,90.6 ; 14.61,92.97 14.61,92.71 ; 28.61,92.97 28.61,92.71 ; 59.74,3.2 60.01,3.2 ; 89.4,103.75 89.13,103.75 ; 146.82,36.36 146.55,36.36 ; 14.61,94.13 14.61,94.4
  BOTTOM w0.5: v1(127,49.59) 127,50.69 127.51,51.2 J3.16 J3.15 131.21,51.2 132.21,52.2 135.01,52.2 135.86,51.36 v1(135.86,51.06) ; 133.36,41.2 133.41,41.2 v1(133.71,40.85) 133.36,41.2 ; 133.36,41.2 J3.5 J3.6 126.91,41.2 126.36,41.75 v1(126.28,41.75) ; 126.32,43.2 J3.8 J3.7 132.61,43.2 v1(133.56,44.15)
  vias: v1(1.51,23.7) v1(1.51,23.7) v1(1.51,20.2) v1(1.51,20.2) v1(1.51,16.7) v1(1.51,16.7) v1(1.51,13.2) v1(1.51,13.2) v1(1.51,8.7) v1(1.51,8.7) v1(1.91,103.1) v1(2,96.05) v1(2,96.05) v1(2.94,45.09) v1(2.94,45.09) v1(4.32,77.59) v1(4.32,77.59) v1(4.51,63.7) v1(4.51,63.7) v1(4.51,60.2) v1(4.51,60.2) v1(4.51,56.7) v1(4.51,56.7) v1(4.51,53.2) v1(4.51,53.2) v1(4.51,49.7) v1(4.51,49.7) v1(4.51,40.7) v1(4.51,40.7) v1(4.51,37.7) v1(4.51,37.7) v1(4.51,34.7) v1(4.51,34.7) v1(4.51,31.7) v1(4.51,31.7) v1(4.83,19.7) v1(4.83,19.7) v1(4.81,16.6) v1(4.81,16.6) v1(5.01,93.7) v1(5.01,93.7) v1(5.01,91.2) v1(5.01,91.2) v1(5.01,80.2) v1(5.01,80.2) v1(5.01,13.2) v1(5.01,13.2) v1(6.44,78.05) v1(6.44,78.05) v1(7.43,46.98) v1(7.43,46.98) v1(7.37,22.24) v1(7.37,22.24) v1(7.37,17.16) v1(7.37,17.16) v1(7.51,80.2) v1(7.51,80.2) v1(7.51,71.2) v1(7.51,71.2) v1(7.51,30.2) v1(7.51,30.2) v1(7.91,77.3) v1(7.91,77.3) v1(8.01,60.2) v1(8.01,60.2) v1(8.01,56.7) v1(8.01,56.7) v1(8.01,53.2) v1(8.01,53.2) v1(8.01,49.7) v1(8.01,49.7) v1(8.51,38.2) v1(8.51,38.2) v1(8.51,8.7) v1(8.51,8.7) v1(9.01,19.8) v1(9.01,19.8) v1(9.1,103.83) v1(9.1,103.83) v1(9.51,16.7) v1(9.51,16.7) v1(9.51,13.2) v1(9.51,13.2) v1(9.65,27.87) v1(9.65,27.87) v1(10.51,80.2) v1(10.51,80.2) v1(11.01,30.2) v1(11.01,30.2) v1(11.51,60.2) v1(11.51,60.2) v1(11.51,56.7) v1(11.51,56.7) v1(11.51,53.2) v1(11.51,53.2) v1(11.71,23.6) v1(11.71,23.6) v1(12.51,97.2) v1(12.51,97.2) v1(12.51,92.7) v1(12.51,92.7) v1(12.51,88.7) v1(12.51,88.7) v1(12.51,85.7) v1(12.51,85.7) v1(12.51,80.2) v1(12.51,80.2) v1(13.51,71.2) v1(13.51,71.2) v1(13.69,7.97) v1(13.69,7.97) v1(14.05,29.01) v1(14.05,29.01) v1(14.43,79.11) v1(14.43,79.11) v1(14.51,36.7) v1(14.51,36.7) v1(14.51,34.7) v1(14.51,34.7) v1(14.51,32.7) v1(14.51,32.7) v1(14.51,30.2) v1(14.51,30.2) v1(15.01,103.7) v1(15.01,103.7) v1(15.2,80.68) v1(15.2,80.68) v1(15.51,43.2) v1(15.51,43.2) v1(15.51,38.7) v1(15.51,38.7) v1(15.98,79.09) v1(15.98,79.09) v1(16.01,8.7) v1(16.01,8.7) v1(16.21,42.6) v1(16.21,42.6) v1(17.01,71.2) v1(17.01,71.2) v1(17.22,67.88) v1(17.22,67.88) v1(17.89,24.89) v1(17.89,24.89) v1(18.01,30.2) v1(18.01,30.2) v1(18.37,61.44) v1(18.37,61.44) v1(18.51,97.7) v1(18.51,97.7) v1(19.01,86.2) v1(19.01,86.2) v1(19.51,88.7) v1(19.51,88.7) v1(20.1,32.74) v1(20.1,32.74) v1(20.19,34.82) v1(20.19,34.82) v1(20.46,36.89) v1(20.46,36.89) v1(20.51,103.7) v1(20.51,103.7) v1(20.51,73.7) v1(20.51,73.7) v1(20.51,71.2) v1(20.51,71.2) v1(20.51,66.7) v1(20.51,66.7) v1(20.51,64.2) v1(20.51,64.2) v1(20.63,28.85) v1(20.63,28.85) v1(20.71,8.7) v1(20.71,8.7) v1(21.51,97.7) v1(21.51,97.7) v1(21.51,30.2) v1(21.51,30.2) v1(22.51,57.5) v1(22.51,57.5) v1(23.01,88.7) v1(23.01,88.7) v1(23.01,86.2) v1(23.01,86.2) v1(23.53,67.84) v1(23.53,67.84) v1(24.01,71.2) v1(24.01,71.2) v1(24.01,18.7) v1(24.01,18.7) v1(24.01,8.7) v1(24.01,8.7) v1(24.13,60.75) v1(24.13,60.75) v1(24.13,60.75) v1(24.13,60.75) v1(24.13,60.75) v1(24.09,59.16) v1(24.09,59.16) v1(24.09,59.16) v1(24.09,59.16) v1(24.09,59.16) v1(25.01,56.6) v1(25.01,56.6) v1(25.01,55.7) v1(25.01,55.7) v1(25.01,54.8) v1(25.01,54.8) v1(25.51,50.3) v1(25.51,11.4) v1(25.51,11.4) v1(26.01,103.7) v1(26.01,103.7) v1(26.34,59.28) v1(26.34,59.28) v1(26.34,59.28) v1(26.34,59.28) v1(26.34,59.28) v1(26.31,54.7) v1(26.31,54.7) v1(26.43,62.52) v1(26.43,62.52) v1(26.43,62.52) v1(26.43,62.52) v1(26.43,62.52) v1(26.37,60.8) v1(26.37,60.8) v1(26.37,60.8) v1(26.37,60.8) v1(26.37,60.8) v1(27,67.87) v1(27,67.87) v1(27.25,32.86) v1(27.25,32.86) v1(27.51,71.2) v1(27.51,71.2) v1(27.86,15.23) v1(27.86,15.23) v1(27.91,16.66) v1(27.91,16.66) v1(28.01,8.7) v1(28.01,8.7) v1(28.08,34.79) v1(28.08,34.79) v1(28.26,28.72) v1(28.26,28.72) v1(28.51,100.2) v1(28.51,100.2) v1(28.51,30.2) v1(28.51,30.2) v1(28.51,17.62) v1(28.51,17.62) v1(28.71,36.95) v1(28.71,36.95) v1(29.33,76.74) v1(29.33,76.74) v1(29.51,87.2) v1(29.51,87.2) v1(30.31,11) v1(30.31,11) v1(30.51,69.7) v1(30.51,69.7) v1(30.51,67.7) v1(30.51,67.7) v1(30.51,65.7) v1(30.51,65.7) v1(30.51,63.7) v1(30.51,63.7) v1(30.51,61.7) v1(30.51,61.7) v1(30.51,32.2) v1(30.51,32.2) v1(30.57,59.25) v1(30.57,59.25) v1(30.69,81.77) v1(30.69,81.77) v1(31.05,72.56) v1(31.05,72.56) v1(31.21,41.36) v1(31.21,41.36) v1(31.41,9.3) v1(31.41,9.3) v1(31.51,103.7) v1(31.51,103.7) v1(31.49,44.98) v1(31.49,44.98) v1(32.01,59.2) v1(32.01,59.2) v1(32.01,57.2) v1(32.01,57.2) v1(32.01,55.2) v1(32.01,55.2) v1(32.01,53.2) v1(32.01,53.2) v1(32.01,51.2) v1(32.01,51.2) v1(32.01,46.7) v1(32.01,46.7) v1(32.01,24.1) v1(32.01,24.1) v1(32.01,24.1) v1(32.01,24.1) v1(32.01,24.1) v1(32.01,24.1) v1(32.01,24.1) v1(32.01,22.3) v1(32.01,22.3) v1(32.01,22.3) v1(32.01,22.3) v1(32.01,22.3) v1(32.01,22.3) v1(32.01,22.3) v1(32.31,60.9) v1(32.51,88.9) v1(32.51,88.9) v1(32.51,34.2) v1(32.51,34.2) v1(33.01,97.2) v1(33.01,97.2) v1(33.01,95.78) v1(33.01,95.78) v1(33.31,88.3) v1(33.31,88.3) v1(33.31,88.3) v1(33.31,88.3) v1(33.31,88.3) v1(33.31,88.3) v1(33.31,85.4) v1(33.31,85.4) v1(33.91,92.44) v1(33.91,92.44) v1(34.18,85.27) v1(34.18,85.27) v1(34.31,86.1) v1(34.31,86.1) v1(34.41,88.3) v1(34.41,88.3) v1(34.41,88.3) v1(34.41,88.3) v1(34.41,88.3) v1(34.41,88.3) v1(34.41,84.4) v1(34.41,84.4) v1(34.49,95.76) v1(34.49,95.76) v1(34.51,36.2) v1(34.51,36.2) v1(35.27,14.07) v1(35.27,14.07) v1(35.5,76.61) v1(35.5,76.61) v1(35.51,73.71) v1(35.51,73.71) v1(35.51,46.7) v1(35.51,46.7) v1(35.79,60.46) v1(35.79,60.46) v1(35.99,92.45) v1(35.99,92.45) v1(36.51,71.2) v1(36.51,71.2) v1(36.51,69.2) v1(36.51,69.2) v1(36.51,57.7) v1(36.51,57.7) v1(36.51,55.2) v1(36.51,55.2) v1(36.51,52.7) v1(36.51,52.7) v1(36.51,48.2) v1(36.51,48.2) v1(36.51,38.2) v1(36.51,38.2) v1(36.61,90.34) v1(36.61,90.34) v1(36.61,90.34) v1(36.61,90.34) v1(36.61,90.34) v1(36.61,90.34) v1(36.71,60.8) v1(36.71,60.8) v1(37.26,73.78) v1(37.26,73.78) v1(37.41,61.4) v1(37.41,61.4) v1(37.56,85.89) v1(37.56,85.89) v1(37.73,87.4) v1(37.73,87.4) v1(37.76,92.45) v1(37.76,92.45) v1(37.76,92.45) v1(37.76,92.45) v1(37.76,92.45) v1(37.76,92.45) v1(37.82,14.73) v1(37.82,14.73) v1(37.97,72.63) v1(37.97,72.63) v1(38.01,40.2) v1(38.01,40.2) v1(38.38,95.08) v1(38.38,95.08) v1(38.42,60.66) v1(38.42,60.66) v1(38.79,77.07) v1(38.79,77.07) v1(38.77,73.66) v1(38.77,73.66) v1(38.88,86.44) v1(38.88,86.44) v1(39.29,79.65) v1(39.29,79.65) v1(39.33,69.65) v1(39.33,69.65) v1(39.53,89.61) v1(39.53,89.61) v1(39.53,89.61) v1(39.53,89.61) v1(39.53,89.61) v1(39.53,89.61) v1(39.51,57.7) v1(39.51,57.7) v1(39.51,55.2) v1(39.51,55.2) v1(39.51,52.7) v1(39.51,52.7) v1(39.91,90.27) v1(39.91,90.27) v1(39.91,90.27) v1(39.91,90.27) v1(39.91,90.27) v1(39.91,90.27) v1(40.12,59.22) v1(40.12,59.22) v1(40.51,42.2) v1(40.51,42.2) v1(40.63,22.18) v1(40.63,22.18) v1(40.9,24.5) v1(40.9,24.5) v1(41.01,27.7) v1(41.01,27.7) v1(42.14,85.49) v1(42.14,85.49) v1(42.52,72.99) v1(42.52,72.99) v1(42.51,57.7) v1(42.51,57.7) v1(42.51,55.2) v1(42.51,55.2) v1(42.51,44.2) v1(42.51,44.2) v1(42.61,76.86) v1(42.61,76.86) v1(43.01,97.2) v1(43.01,97.2) v1(43.13,22.09) v1(43.13,22.09) v1(43.16,15.55) v1(43.16,15.55) v1(43.25,73.73) v1(43.25,73.73) v1(43.21,26.5) v1(43.21,26.5) v1(43.51,71.2) v1(43.51,71.2) v1(43.51,69.2) v1(43.51,69.2) v1(43.68,11.13) v1(43.68,11.13) v1(44.51,46.2) v1(44.51,46.2) v1(45.02,77.55) v1(45.02,77.55) v1(45.3,90.89) v1(45.3,90.89) v1(45.3,90.89) v1(45.3,90.89) v1(45.3,90.89) v1(45.3,90.89) v1(45.37,92.36) v1(45.37,92.36) v1(45.51,57.7) v1(45.51,57.7) v1(45.74,89.82) v1(45.74,89.82) v1(45.78,88.33) v1(45.78,88.33) v1(46.16,27.09) v1(46.16,27.09) v1(46.17,25.62) v1(46.17,25.62) v1(46.51,48.2) v1(46.51,48.2) v1(46.51,32.7) v1(46.51,32.7) v1(46.81,70.16) v1(46.81,70.16) v1(46.88,88.22) v1(46.88,88.22) v1(46.9,86.45) v1(46.9,86.45) v1(47.34,92.28) v1(47.34,92.28) v1(47.31,90.94) v1(47.31,90.94) v1(47.31,90) v1(47.31,90) v1(47.72,100.29) v1(47.72,100.29) v1(47.72,97.24) v1(47.72,97.24) v1(47.76,95.04) v1(47.92,12.18) v1(47.92,12.18) v1(48.42,93.08) v1(48.42,93.08) v1(48.42,86.51) v1(48.42,86.51) v1(48.91,91.66) v1(48.91,91.66) v1(48.92,59.98) v1(48.92,59.98) v1(49.56,88.65) v1(49.56,88.65) v1(49.62,86.48) v1(49.62,86.48) v1(49.91,72.1) v1(49.91,72.1) v1(50.01,52.2) v1(50.01,52.2) v1(50.01,28.7) v1(50.01,28.7) v1(50.15,71.3) v1(50.15,71.3) v1(50.42,39.22) v1(50.42,39.22) v1(50.55,98.3) v1(50.55,98.3) v1(50.87,68.86) v1(50.87,68.86) v1(51.15,90.38) v1(51.15,90.38) v1(51.19,88.57) v1(51.19,88.57) v1(51.21,32.9) v1(51.21,32.9) v1(51.4,43.35) v1(51.4,43.35) v1(51.59,91.43) v1(51.59,91.43) v1(51.62,13.47) v1(51.62,13.47) v1(51.76,93.68) v1(51.76,93.68) v1(52.01,54.2) v1(52.01,54.2) v1(52.08,98.46) v1(52.08,98.46) v1(52.91,88.39) v1(52.91,88.39) v1(53.02,93.34) v1(53.02,93.34) v1(53.02,91.81) v1(53.02,91.81) v1(53.07,47.76) v1(53.07,47.76) v1(53.12,14.52) v1(53.12,14.52) v1(53.51,32.7) v1(53.51,32.7) v1(53.51,28.7) v1(53.51,28.7) v1(53.51,24.7) v1(53.51,24.7) v1(54.01,56.2) v1(54.01,56.2) v1(54.24,93.34) v1(54.24,93.34) v1(54.24,91.81) v1(54.24,91.81) v1(54.38,51.42) v1(54.38,51.42) v1(54.38,51.42) v1(54.38,51.42) v1(54.38,51.42) v1(54.38,51.42) v1(54.38,51.42) v1(54.73,43.46) v1(54.73,43.46) v1(54.72,38.19) v1(54.72,38.19) v1(54.85,92.63) v1(54.85,92.63) v1(55.09,77.43) v1(55.09,77.43) v1(55.16,24.92) v1(55.16,24.92) v1(55.29,26.53) v1(55.29,26.53) v1(55.46,93.34) v1(55.46,93.34) v1(55.46,91.81) v1(55.46,91.81) v1(55.9,98.57) v1(55.9,98.57) v1(56.01,58.2) v1(56.01,58.2) v1(56.07,16.25) v1(56.07,16.25) v1(56.07,12.85) v1(56.07,12.85) v1(56.33,92.12) v1(56.33,92.12) v1(56.76,47.78) v1(56.76,47.78) v1(56.76,47.78) v1(56.76,47.78) v1(56.76,47.78) v1(56.76,47.78) v1(56.76,47.78) v1(56.7,44.38) v1(56.7,44.38) v1(56.82,53.22) v1(56.82,53.22) v1(56.82,53.22) v1(56.82,53.22) v1(56.82,53.22) v1(56.82,53.22) v1(56.82,53.22) v1(56.8,51.38) v1(56.8,51.38) v1(56.8,51.38) v1(56.8,51.38) v1(56.8,51.38) v1(56.8,51.38) v1(56.8,51.38) v1(56.96,97.33) v1(56.96,97.33) v1(56.98,95.81) v1(56.98,95.81) v1(56.98,94.3) v1(56.98,94.3) v1(57.15,87.43) v1(57.15,87.43) v1(57.09,39.3) v1(57.09,39.3) v1(57.48,99.28) v1(57.48,99.28) v1(57.47,75.91) v1(57.47,75.91) v1(57.92,101.72) v1(57.92,101.72) v1(58.22,97.8) v1(58.22,97.8) v1(58.35,75.56) v1(58.35,75.56) v1(58.39,90.73) v1(58.39,90.73) v1(58.59,92.7) v1(58.59,92.7) v1(58.82,93.98) v1(58.82,93.98) v1(59.84,93.92) v1(59.84,93.92) v1(59.8,91.1) v1(59.8,91.1) v1(59.83,76.07) v1(59.83,76.07) v1(60.05,74.7) v1(60.05,74.7) v1(60.25,92.74) v1(60.25,92.74) v1(60.34,28.71) v1(60.34,28.71) v1(60.51,58.2) v1(60.51,58.2) v1(60.51,55.7) v1(60.51,55.7) v1(60.51,53.2) v1(60.51,53.2) v1(60.51,50.7) v1(60.51,50.7) v1(60.51,48.2) v1(60.51,48.2) v1(60.51,46.6) v1(60.51,46.6) v1(60.51,43.2) v1(60.51,43.2) v1(60.51,36.2) v1(60.51,36.2) v1(60.71,100.3) v1(60.71,100.3) v1(60.72,98.65) v1(60.72,98.65) v1(60.72,72.02) v1(60.72,72.02) v1(60.75,70.06) v1(60.75,70.06) v1(60.7,41.64) v1(60.7,41.64) v1(60.69,31.03) v1(60.69,31.03) v1(60.87,97) v1(60.87,97) v1(60.94,23.51) v1(60.94,23.51) v1(61.21,94.17) v1(61.21,94.17) v1(61.41,37.1) v1(61.41,37.1) v1(61.51,11.2) v1(61.51,11.2) v1(61.61,17.3) v1(61.61,17.3) v1(61.61,17.3) v1(61.61,17.3) v1(61.61,17.3) v1(61.61,17.3) v1(61.61,17.3) v1(62,64.2) v1(62,64.2) v1(62.38,90.29) v1(62.38,90.29) v1(62.38,90.29) v1(62.38,90.29) v1(62.37,89.55) v1(62.37,89.55) v1(62.37,89.55) v1(62.37,89.55) v1(62.47,97.68) v1(62.47,97.68) v1(62.78,31.2) v1(62.78,31.2) v1(63.01,11.2) v1(63.01,11.2) v1(63.22,68.35) v1(63.22,68.35) v1(63.38,22.9) v1(63.38,22.9) v1(63.51,97.68) v1(63.51,97.68) v1(63.51,17.5) v1(63.51,17.5) v1(64.01,26.7) v1(64.01,26.7) v1(64.62,96.97) v1(64.62,96.97) v1(64.57,93.67) v1(64.57,93.67) v1(64.71,90.86) v1(64.71,90.86) v1(64.71,74) v1(64.71,74) v1(64.71,72) v1(64.71,72) v1(64.71,70) v1(64.71,70) v1(65.04,7.9) v1(65.04,7.9) v1(65.1,12.28) v1(65.1,12.28) v1(65.46,36.59) v1(65.46,36.59) v1(65.51,66.2) v1(65.51,66.2) v1(65.51,63.3) v1(65.51,63.3) v1(65.51,60.7) v1(65.51,60.7) v1(65.51,58.2) v1(65.51,58.2) v1(65.51,55.7) v1(65.51,55.7) v1(65.51,53.2) v1(65.51,53.2) v1(65.51,50.7) v1(65.51,50.7) v1(65.51,48.2) v1(65.51,48.2) v1(65.51,45.7) v1(65.51,45.7) v1(65.51,43.2) v1(65.51,43.2) v1(65.76,94.14) v1(65.76,94.14) v1(66.01,97.1) v1(66.01,97.1) v1(66.01,93.43) v1(66.01,93.43) v1(66.01,1.7) v1(66.01,1.7) v1(66.29,9.58) v1(66.29,9.58) v1(66.39,101.88) v1(66.39,101.88) v1(66.39,101.88) v1(66.39,101.88) v1(66.39,101.88) v1(66.39,101.88) v1(66.39,101.88) v1(66.39,101.88) v1(66.39,101.88) v1(66.7,35.06) v1(66.7,35.06) v1(67.41,69.3) v1(67.41,69.3) v1(67.47,94.24) v1(67.47,94.24) v1(67.51,30.2) v1(67.51,30.2) v1(67.71,74.32) v1(67.71,74.32) v1(67.68,70.93) v1(67.68,70.93) v1(67.98,93.47) v1(67.98,93.47) v1(67.98,93.47) v1(67.98,93.47) v1(68.14,87.05) v1(68.14,87.05) v1(68.14,87.05) v1(68.14,87.05) v1(68.14,87.05) v1(68.14,87.05) v1(68.13,86.06) v1(68.13,86.06) v1(68.13,86.06) v1(68.13,86.06) v1(68.13,86.06) v1(68.13,86.06) v1(68.17,101.89) v1(68.19,99.8) v1(68.23,25.57) v1(68.23,25.57) v1(68.41,16.9) v1(68.41,16.9) v1(68.41,16.9) v1(68.41,16.9) v1(68.41,16.9) v1(68.41,16.9) v1(68.41,16.9) v1(68.77,28.46) v1(68.77,28.46) v1(69.01,4.2) v1(69.01,4.2) v1(69.01,1.7) v1(69.01,1.7) v1(69.09,87.07) v1(69.09,87.07) v1(69.09,87.07) v1(69.09,87.07) v1(69.09,87.07) v1(69.09,87.07) v1(69.09,86.05) v1(69.09,86.05) v1(69.09,86.05) v1(69.09,86.05) v1(69.09,86.05) v1(69.09,86.05) v1(69.23,98.03) v1(69.23,98.03) v1(69.51,73.3) v1(69.51,73.3) v1(69.51,73.3) v1(69.7,14.39) v1(69.7,14.39) v1(70.01,69.2) v1(70.01,69.2) v1(70.01,66.2) v1(70.01,66.2) v1(70.01,63.4) v1(70.01,63.4) v1(70.01,60.7) v1(70.01,60.7) v1(70.01,58.2) v1(70.01,58.2) v1(70.01,55.7) v1(70.01,55.7) v1(70.01,53.2) v1(70.01,53.2) v1(70.01,50.7) v1(70.01,50.7) v1(70.01,48.2) v1(70.01,48.2) v1(70.01,45.7) v1(70.01,45.7) v1(70.01,43.2) v1(70.01,43.2) v1(70.01,37.7) v1(70.01,37.7) v1(70.01,35.2) v1(70.01,35.2) v1(70.1,88.08) v1(70.1,88.08) v1(70.1,88.08) v1(70.1,88.08) v1(70.1,88.08) v1(70.1,88.08) v1(70.1,87.07) v1(70.1,87.07) v1(70.1,87.07) v1(70.1,87.07) v1(70.1,87.07) v1(70.1,87.07) v1(70.1,86.05) v1(70.1,86.05) v1(70.1,86.05) v1(70.1,86.05) v1(70.1,86.05) v1(70.1,86.05) v1(70.37,101.88) v1(71.42,78.16) v1(71.42,78.16) v1(71.41,73.3) v1(71.41,73.3) v1(71.8,13.89) v1(71.8,13.89) v1(72.01,7.2) v1(72.01,7.2) v1(72.01,4.2) v1(72.01,4.2) v1(72.01,1.7) v1(72.01,1.7) v1(72.31,101) v1(72.31,101) v1(72.31,10.5) v1(72.31,10.5) v1(73.15,74.6) v1(73.15,74.6) v1(73.12,52.87) v1(73.12,52.87) v1(73.12,47.79) v1(73.12,47.79) v1(73.12,42.71) v1(73.12,42.71) v1(73.12,37.63) v1(73.12,37.63) v1(73.12,27.47) v1(73.12,27.47) v1(73.12,22.39) v1(73.12,22.39) v1(73.41,16.9) v1(73.41,16.9) v1(73.41,16.9) v1(73.41,16.9) v1(73.41,16.9) v1(73.41,16.9) v1(73.41,16.9) v1(73.51,98.03) v1(73.51,98.03) v1(73.61,10.6) v1(73.61,10.6) v1(73.84,77.89) v1(73.84,77.89) v1(73.82,14.03) v1(73.82,14.03) v1(74.56,84.7) v1(74.56,84.7) v1(74.56,84.7) v1(74.56,84.7) v1(74.71,94.2) v1(74.71,94.2) v1(74.81,96.7) v1(74.81,96.7) v1(74.81,96.7) v1(74.81,96.7) v1(75.01,1.7) v1(75.01,1.7) v1(75.09,86.78) v1(75.09,86.78) v1(75.09,86.78) v1(75.09,86.78) v1(75.17,88.36) v1(75.17,88.36) v1(75.17,88.36) v1(75.17,88.36) v1(75.51,72.2) v1(75.51,72.2) v1(75.51,67.2) v1(75.51,67.2) v1(75.66,60.49) v1(75.66,60.49) v1(75.66,55.41) v1(75.66,55.41) v1(75.66,50.33) v1(75.66,50.33) v1(75.66,45.25) v1(75.66,45.25) v1(75.66,35.09) v1(75.66,35.09) v1(75.66,30.01) v1(75.66,30.01) v1(75.66,24.93) v1(75.66,24.93) v1(75.99,8.42) v1(75.99,8.42) v1(75.99,8.42) v1(75.99,8.42) v1(75.99,8.42) v1(75.99,8.42) v1(76.13,4.13) v1(76.13,4.13) v1(76.13,4.13) v1(76.13,4.13) v1(77.01,103.7) v1(77.01,103.7) v1(77.01,99.7) v1(77.01,99.7) v1(77.01,98.7) v1(77.01,98.7) v1(77.01,98.7) v1(77.01,98.7) v1(77.43,8.31) v1(77.43,8.31) v1(77.43,8.31) v1(77.43,8.31) v1(77.43,8.31) v1(77.43,8.31) v1(77.51,92.2) v1(77.51,92.2) v1(77.6,88.71) v1(77.6,88.71) v1(78.01,69.7) v1(78.01,69.7) v1(78.2,63.03) v1(78.2,63.03) v1(78.2,57.95) v1(78.2,57.95) v1(78.2,52.87) v1(78.2,52.87) v1(78.2,47.79) v1(78.2,47.79) v1(78.2,42.71) v1(78.2,42.71) v1(78.2,37.63) v1(78.2,37.63) v1(78.2,27.47) v1(78.2,27.47) v1(78.2,22.39) v1(78.2,22.39) v1(78.61,16.9) v1(78.61,16.9) v1(78.61,16.9) v1(78.61,16.9) v1(78.61,16.9) v1(78.61,16.9) v1(78.61,16.9) v1(79.51,84.2) v1(79.51,84.2) v1(79.47,14.7) v1(79.47,14.7) v1(80.51,72.2) v1(80.51,72.2) v1(80.51,67.2) v1(80.51,67.2) v1(80.74,60.49) v1(80.74,60.49) v1(80.74,55.41) v1(80.74,55.41) v1(80.74,50.33) v1(80.74,50.33) v1(80.74,45.25) v1(80.74,45.25) v1(80.74,35.09) v1(80.74,35.09) v1(80.74,30.01) v1(80.74,30.01) v1(80.74,24.93) v1(80.74,24.93) v1(81.11,94.1) v1(81.11,94.1) v1(81.11,94.1) v1(81.11,94.1) v1(81.66,14.14) v1(81.66,14.14) v1(82.01,85.7) v1(82.01,85.7) v1(82.01,83.7) v1(82.01,83.7) v1(82.01,81.7) v1(82.01,81.7) v1(82.61,16.9) v1(82.61,16.9) v1(82.61,16.9) v1(82.61,16.9) v1(82.61,16.9) v1(82.61,16.9) v1(82.61,16.9) v1(83.01,103.7) v1(83.01,103.7) v1(83.28,63.03) v1(83.28,63.03) v1(83.28,57.95) v1(83.28,57.95) v1(83.28,52.87) v1(83.28,52.87) v1(83.28,47.79) v1(83.28,47.79) v1(83.28,42.71) v1(83.28,42.71) v1(83.28,37.63) v1(83.28,37.63) v1(83.28,27.47) v1(83.28,27.47) v1(83.61,14.1) v1(83.61,14.1) v1(84.01,81.7) v1(84.01,81.7) v1(84.61,78.26) v1(84.61,78.26) v1(84.88,8.25) v1(84.88,8.25) v1(84.88,8.25) v1(84.88,8.25) v1(84.88,8.25) v1(84.88,8.25) v1(85.45,13.93) v1(85.45,13.93) v1(85.82,60.49) v1(85.82,60.49) v1(85.82,55.41) v1(85.82,55.41) v1(85.82,50.33) v1(85.82,50.33) v1(85.82,45.25) v1(85.82,45.25) v1(85.82,35.09) v1(85.82,35.09) v1(85.82,30.01) v1(85.82,30.01) v1(85.82,24.93) v1(85.82,24.93) v1(86.01,103.7) v1(86.01,103.7) v1(86.01,72.2) v1(86.01,72.2) v1(86.01,67.2) v1(86.01,67.2) v1(86.61,16.9) v1(86.61,16.9) v1(86.61,16.9) v1(86.61,16.9) v1(86.61,16.9) v1(86.61,16.9) v1(86.61,16.9) v1(88.41,81.5) v1(88.41,81.5) v1(88.41,79) v1(88.41,79) v1(88.41,79) v1(88.41,79) v1(88.41,79) v1(88.41,79) v1(88.41,79) v1(88.36,68.11) v1(88.36,68.11) v1(88.36,63.03) v1(88.36,63.03) v1(88.36,57.95) v1(88.36,57.95) v1(88.36,52.87) v1(88.36,52.87) v1(88.36,47.79) v1(88.36,47.79) v1(88.36,42.71) v1(88.36,37.63) v1(88.36,37.63) v1(88.36,35.09) v1(88.36,35.09) v1(88.36,27.47) v1(88.36,27.47) v1(88.91,84.5) v1(88.91,84.5) v1(89.81,78.3) v1(89.81,78.3) v1(89.91,88.5) v1(89.91,88.5) v1(90.01,94.7) v1(90.01,94.7) v1(90.01,92.2) v1(90.01,92.2) v1(90.01,89.7) v1(90.01,89.7) v1(90.51,98.7) v1(90.51,98.7) v1(90.61,16.9) v1(90.61,16.9) v1(90.61,16.9) v1(90.61,16.9) v1(90.61,16.9) v1(90.61,16.9) v1(90.61,16.9) v1(90.9,60.49) v1(90.9,60.49) v1(90.9,55.41) v1(90.9,55.41) v1(90.9,50.33) v1(90.9,50.33) v1(90.9,45.25) v1(90.9,45.25) v1(90.9,30.01) v1(90.9,30.01) v1(91.86,78.29) v1(91.86,78.29) v1(91.89,4.91) v1(91.89,4.91) v1(91.89,4.91) v1(91.89,4.91) v1(91.89,4.91) v1(91.89,4.91) v1(93.01,74.3) v1(93.01,74.3) v1(93.01,14.3) v1(93.01,14.3) v1(93.02,13.52) v1(93.02,13.52) v1(93.03,8.88) v1(93.03,8.88) v1(93.31,95) v1(93.31,95) v1(93.41,89) v1(93.41,89) v1(93.44,78.27) v1(93.44,78.27) v1(93.55,16.85) v1(93.55,16.85) v1(93.55,16.85) v1(93.55,16.85) v1(93.55,16.85) v1(93.55,16.85) v1(93.55,16.85) v1(93.95,3.34) v1(93.95,3.34) v1(94.01,74.3) v1(94.01,74.3) v1(93.97,19.69) v1(93.97,19.69) v1(93.97,19.69) v1(93.97,19.69) v1(93.97,19.69) v1(93.97,19.69) v1(93.97,19.69) v1(94.34,54.35) v1(94.34,54.35) v1(94.29,45.35) v1(94.29,45.35) v1(94.34,28.08) v1(94.34,28.08) v1(94.31,8) v1(94.31,8) v1(94.44,65.72) v1(94.44,65.72) v1(94.44,61.41) v1(94.44,61.41) v1(94.41,25.9) v1(94.41,25.9) v1(94.49,69.99) v1(94.49,69.99) v1(94.5,13.53) v1(94.5,13.53) v1(95.03,91.38) v1(95.03,91.38) v1(95.79,52.2) v1(95.79,52.2) v1(95.93,6.14) v1(95.93,6.14) v1(95.95,4.5) v1(95.95,4.5) v1(95.98,50.73) v1(95.98,50.73) v1(96.06,47.05) v1(96.06,47.05) v1(96.01,13.6) v1(96.01,13.6) v1(96.14,42.04) v1(96.14,42.04) v1(96.18,9) v1(96.18,9) v1(96.17,2.15) v1(96.17,2.15) v1(96.41,86) v1(96.41,86) v1(96.48,44.33) v1(96.48,44.33) v1(96.61,22) v1(96.61,22) v1(96.73,37.73) v1(96.73,37.73) v1(96.71,33.4) v1(96.71,33.4) v1(96.74,30.13) v1(96.74,30.13) v1(96.73,25.83) v1(96.73,25.83) v1(97.35,86.62) v1(97.35,86.62) v1(97.35,86.62) v1(97.35,86.62) v1(97.35,86.62) v1(97.35,86.62) v1(97.35,86.62) v1(97.73,46.5) v1(97.73,46.5) v1(97.8,49.37) v1(97.8,49.37) v1(97.76,9) v1(97.76,9) v1(97.96,43.17) v1(97.96,43.17) v1(98.01,94.9) v1(98.01,94.9) v1(98.05,2.64) v1(98.05,2.64) v1(98.08,92.21) v1(98.08,92.21) v1(98.52,101.13) v1(98.52,101.13) v1(98.48,86.59) v1(98.48,86.59) v1(98.48,86.59) v1(98.48,86.59) v1(98.86,11.37) v1(98.86,11.37) v1(99.39,3.76) v1(99.39,3.76) v1(99.93,81.57) v1(99.93,81.57) v1(100.03,74.48) v1(100.03,74.48) v1(100.15,54.41) v1(100.15,54.41) v1(100.15,54.41) v1(100.15,54.41) v1(100.1,6.29) v1(100.1,6.29) v1(100.21,46.2) v1(100.21,46.2) v1(100.21,46.2) v1(100.21,46.2) v1(100.19,10.7) v1(100.19,10.7) v1(100.31,56.33) v1(100.31,56.33) v1(100.31,56.33) v1(100.31,56.33) v1(100.29,48.2) v1(100.29,48.2) v1(100.29,48.2) v1(100.29,48.2) v1(100.4,50.08) v1(100.4,50.08) v1(100.4,50.08) v1(100.4,50.08) v1(100.4,44.1) v1(100.4,44.1) v1(100.4,44.1) v1(100.4,44.1) v1(100.39,28.26) v1(100.39,28.26) v1(100.39,28.26) v1(100.39,28.26) v1(100.44,24.52) v1(100.44,24.52) v1(100.44,24.52) v1(100.44,24.52) v1(100.49,32.28) v1(100.49,32.28) v1(100.49,32.28) v1(100.49,32.28) v1(100.47,26.43) v1(100.47,26.43) v1(100.47,26.43) v1(100.47,26.43) v1(100.58,92.24) v1(100.58,92.24) v1(100.63,86.64) v1(100.63,86.64) v1(100.63,86.64) v1(100.63,86.64) v1(100.59,79.86) v1(100.59,79.86) v1(100.57,68.95) v1(100.57,68.95) v1(100.57,34.23) v1(100.57,34.23) v1(100.57,34.23) v1(100.57,34.23) v1(100.62,30.32) v1(100.62,30.32) v1(100.62,30.32) v1(100.62,30.32) v1(100.67,42.11) v1(100.67,42.11) v1(100.67,42.11) v1(100.67,42.11) v1(100.95,3.99) v1(100.95,3.99) v1(100.98,77.98) v1(100.98,77.98) v1(101.11,104.2) v1(101.11,104.2) v1(101.41,52.24) v1(101.41,52.24) v1(101.45,37.36) v1(101.45,37.36) v1(101.45,37.36) v1(101.45,37.36) v1(101.7,86.56) v1(101.7,86.56) v1(101.7,86.56) v1(101.7,86.56) v1(101.85,46.49) v1(101.85,46.49) v1(101.85,46.49) v1(101.85,46.49) v1(101.93,56.71) v1(101.93,56.71) v1(101.93,56.71) v1(101.93,56.71) v1(102.01,10.4) v1(102.01,10.4) v1(102.2,54.47) v1(102.2,54.47) v1(102.2,54.47) v1(102.2,54.47) v1(102.27,76.66) v1(102.27,76.66) v1(102.48,48.55) v1(102.48,48.55) v1(102.48,48.55) v1(102.48,48.55) v1(102.56,81.12) v1(102.56,81.12) v1(102.6,50.16) v1(102.6,50.16) v1(102.6,50.16) v1(102.6,50.16) v1(102.73,8.02) v1(102.73,8.02) v1(102.85,58.89) v1(102.85,58.89) v1(102.83,17.24) v1(102.83,17.24) v1(102.92,83.06) v1(102.92,83.06) v1(103.08,86.02) v1(103.08,86.02) v1(103.08,86.02) v1(103.08,86.02) v1(103.17,68.81) v1(103.17,68.81) v1(103.2,56.82) v1(103.2,56.82) v1(103.2,56.82) v1(103.2,56.82) v1(103.29,44.26) v1(103.29,44.26) v1(103.29,44.26) v1(103.29,44.26) v1(103.6,101.13) v1(103.6,101.13) v1(103.6,96.05) v1(103.6,96.05) v1(103.65,64.9) v1(103.65,64.9) v1(103.82,42.18) v1(103.82,42.18) v1(103.82,42.18) v1(103.82,42.18) v1(103.81,18) v1(103.81,18) v1(104.41,82.8) v1(104.41,82.8) v1(104.45,80.97) v1(104.45,80.97) v1(104.93,78.37) v1(104.93,78.37) v1(105.11,15.9) v1(105.11,15.9) v1(105.44,68.8) v1(105.44,68.8) v1(105.59,76.45) v1(105.59,76.45) v1(105.66,53.01) v1(105.66,53.01) v1(105.66,53.01) v1(105.66,53.01) v1(106.13,12.31) v1(106.13,12.31) v1(106.21,104.2) v1(106.21,104.2) v1(106.31,83.2) v1(106.31,83.2) v1(106.31,24.5) v1(106.31,24.5) v1(106.41,81.6) v1(106.41,81.6) v1(106.4,80.12) v1(106.4,80.12) v1(106.4,77.58) v1(106.4,77.58) v1(106.5,74.14) v1(106.5,74.14) v1(106.47,60.95) v1(106.47,60.95) v1(106.47,58.41) v1(106.47,58.41) v1(106.47,55.87) v1(106.47,55.87) v1(106.48,46.87) v1(106.48,46.87) v1(106.77,62.25) v1(106.77,62.25) v1(107.06,32.38) v1(107.06,32.38) v1(107.06,32.38) v1(107.06,32.38) v1(107.05,29.39) v1(107.05,29.39) v1(107.05,29.39) v1(107.05,29.39) v1(107.14,49.17) v1(107.14,49.17) v1(107.25,78.1) v1(107.25,78.1) v1(107.25,78.1) v1(107.25,78.1) v1(107.31,86.2) v1(107.31,86.2) v1(107.33,75.81) v1(107.33,75.81) v1(107.33,75.81) v1(107.33,75.81) v1(107.86,80.23) v1(107.86,80.23) v1(107.86,80.23) v1(107.86,80.23) v1(107.88,79.17) v1(107.88,79.17) v1(107.88,79.17) v1(107.88,79.17) v1(107.94,25.82) v1(107.94,25.82) v1(108.01,12.71) v1(108.01,12.71) v1(108.1,92.19) v1(108.1,92.19) v1(108.21,24.5) v1(108.21,24.5) v1(108.18,11.27) v1(108.18,11.27) v1(108.68,96.05) v1(108.68,96.05) v1(108.91,44.5) v1(109.01,60.95) v1(109.01,60.95) v1(109.01,58.41) v1(109.01,58.41) v1(109.21,51.27) v1(109.21,51.27) v1(109.21,10.6) v1(109.21,10.6) v1(109.61,91.1) v1(109.61,91.1) v1(109.61,89.5) v1(109.61,89.5) v1(109.61,87.8) v1(109.61,87.8) v1(109.61,85.9) v1(109.61,85.9) v1(109.57,30.91) v1(109.57,30.91) v1(109.57,30.91) v1(109.57,30.91) v1(110.14,46.55) v1(110.14,46.55) v1(110.1,7.58) v1(110.1,7.58) v1(110.8,34.21) v1(110.8,34.21) v1(110.8,34.21) v1(110.8,34.21) v1(111.21,104.2) v1(111.21,104.2) v1(111.18,17.03) v1(111.18,17.03) v1(111.28,72.08) v1(111.28,72.08) v1(111.41,2.5) v1(111.41,2.5) v1(111.55,60.95) v1(111.55,60.95) v1(112.22,72.9) v1(112.22,72.9) v1(112.41,88.6) v1(112.41,88.6) v1(112.36,87.03) v1(112.36,87.03) v1(112.4,7.6) v1(112.4,7.6) v1(113.22,16.98) v1(113.22,16.98) v1(113.51,82) v1(113.51,82) v1(113.51,82) v1(113.51,82) v1(113.51,82) v1(113.51,82) v1(113.53,76.51) v1(113.53,76.51) v1(113.53,76.51) v1(113.53,76.51) v1(113.53,76.51) v1(113.53,76.51) v1(113.53,76.51) v1(113.53,75.49) v1(113.53,75.49) v1(113.53,75.49) v1(113.53,75.49) v1(113.53,75.49) v1(113.53,75.49) v1(113.53,75.49) v1(113.53,74.47) v1(113.53,74.47) v1(113.53,74.47) v1(113.53,74.47) v1(113.53,74.47) v1(113.53,74.47) v1(113.53,74.47) v1(113.76,88.43) v1(113.76,88.43) v1(113.76,85.89) v1(113.76,85.89) v1(113.87,46.96) v1(113.87,46.96) v1(113.98,83.06) v1(113.98,83.06) v1(114.05,12.08) v1(114.05,12.08) v1(114.01,10.9) v1(114.01,10.9) v1(114.21,4.85) v1(114.21,4.85) v1(114.55,76.51) v1(114.55,76.51) v1(114.55,76.51) v1(114.55,76.51) v1(114.55,76.51) v1(114.55,76.51) v1(114.55,76.51) v1(114.55,75.49) v1(114.55,75.49) v1(114.55,75.49) v1(114.55,75.49) v1(114.55,75.49) v1(114.55,75.49) v1(114.55,75.49) v1(114.55,74.47) v1(114.55,74.47) v1(114.55,74.47) v1(114.55,74.47) v1(114.55,74.47) v1(114.55,74.47) v1(114.55,74.47) v1(114.65,30.91) v1(114.65,30.91) v1(114.65,30.91) v1(114.65,30.91) v1(114.77,16.09) v1(114.77,16.09) v1(114.81,2.5) v1(114.81,2.5) v1(115.11,62.69) v1(115.11,62.69) v1(115.21,13.2) v1(115.21,13.2) v1(115.21,12.1) v1(115.21,12.1) v1(115.22,7.14) v1(115.22,7.14) v1(115.32,55.83) v1(115.32,55.83) v1(115.56,76.51) v1(115.56,76.51) v1(115.56,76.51) v1(115.56,76.51) v1(115.56,76.51) v1(115.56,76.51) v1(115.56,76.51) v1(115.56,75.49) v1(115.56,75.49) v1(115.56,75.49) v1(115.56,75.49) v1(115.56,75.49) v1(115.56,75.49) v1(115.56,75.49) v1(115.56,74.47) v1(115.56,74.47) v1(115.56,74.47) v1(115.56,74.47) v1(115.56,74.47) v1(115.56,74.47) v1(115.56,74.47) v1(115.81,44.41) v1(115.81,44.41) v1(116.21,20.16) v1(116.21,20.16) v1(116.31,104.2) v1(116.31,104.2) v1(116.35,58.59) v1(116.35,58.59) v1(116.29,21.75) v1(116.29,21.75) v1(116.41,85.4) v1(116.41,85.4) v1(116.64,57.05) v1(116.64,57.05) v1(116.64,57.05) v1(116.64,57.05) v1(117.11,78.28) v1(117.11,78.28) v1(117.22,32.38) v1(117.22,32.38) v1(117.22,32.38) v1(117.22,32.38) v1(117.21,29.39) v1(117.21,29.39) v1(117.21,29.39) v1(117.21,29.39) v1(117.29,60.64) v1(117.29,60.64) v1(117.69,38.46) v1(117.69,38.46) v1(117.69,38.46) v1(117.69,38.46) v1(118.04,16.08) v1(118.04,16.08) v1(117.99,13.97) v1(117.99,13.97) v1(118.41,61.4) v1(118.41,61.4) v1(118.52,63.29) v1(118.52,63.29) v1(118.62,3.55) v1(118.62,3.55) v1(118.84,101.13) v1(118.84,101.13) v1(118.84,96.05) v1(118.84,96.05) v1(118.81,93.1) v1(118.81,93.1) v1(118.81,93.1) v1(118.81,93.1) v1(118.81,93.1) v1(118.81,93.1) v1(118.81,93.1) v1(119.25,24.74) v1(119.25,24.74) v1(119.17,8.55) v1(119.17,8.55) v1(119.4,67.27) v1(119.4,67.27) v1(119.64,4.97) v1(119.64,4.97) v1(119.75,38.45) v1(119.75,38.45) v1(119.75,38.45) v1(119.75,38.45) v1(119.73,30.91) v1(119.73,30.91) v1(119.73,30.91) v1(119.73,30.91) v1(119.75,21.33) v1(119.75,21.33) v1(119.91,47.5) v1(119.91,47.5) v1(119.91,45.5) v1(119.91,45.5) v1(119.91,45.5) v1(119.91,45.5) v1(119.91,45.5) v1(119.91,45.5) v1(120.01,49.5) v1(120.01,49.5) v1(120.01,49.5) v1(120.01,49.5) v1(120.11,53.9) v1(120.11,53.9) v1(120.11,53.9) v1(120.11,53.9) v1(120.25,60.71) v1(120.25,60.71) v1(120.21,58.6) v1(120.21,58.6) v1(120.21,56.9) v1(120.21,56.9) v1(120.21,56.9) v1(120.21,56.9) v1(120.3,3.57) v1(120.3,3.57) v1(120.79,63.34) v1(120.79,63.34) v1(121.08,81.61) v1(121.08,81.61) v1(121.08,81.61) v1(121.08,81.61) v1(121.09,64.81) v1(121.09,64.81) v1(121.23,80.58) v1(121.23,80.58) v1(121.23,80.58) v1(121.23,80.58) v1(121.19,67.82) v1(121.19,67.82) v1(121.27,10.43) v1(121.27,10.43) v1(121.41,104.2) v1(121.41,104.2) v1(121.55,24.29) v1(121.55,24.29) v1(121.55,24.29) v1(121.55,24.29) v1(121.76,78.67) v1(121.76,78.67) v1(121.76,78.67) v1(121.76,78.67) v1(121.76,78.67) v1(121.76,78.67) v1(121.7,74.15) v1(121.7,74.15) v1(121.7,74.15) v1(121.7,74.15) v1(121.7,74.15) v1(121.7,74.15) v1(121.8,81.21) v1(121.8,81.21) v1(121.8,81.21) v1(121.8,81.21) v1(121.8,81.21) v1(121.8,81.21) v1(122.11,16.3) v1(122.11,16.3) v1(122.21,85.5) v1(122.21,85.5) v1(122.3,32.38) v1(122.3,32.38) v1(122.3,32.38) v1(122.3,32.38) v1(122.29,29.39) v1(122.29,29.39) v1(122.29,29.39) v1(122.29,29.39) v1(122.46,7.16) v1(122.46,7.16) v1(122.5,3.03) v1(122.5,3.03) v1(122.71,23.2) v1(122.71,23.2) v1(122.76,57.1) v1(122.76,57.1) v1(122.76,57.1) v1(122.76,57.1) v1(122.94,78.75) v1(122.94,78.75) v1(122.94,78.75) v1(122.94,78.75) v1(122.94,78.75) v1(122.94,78.75) v1(123.01,96) v1(123.01,96) v1(123.01,82.1) v1(123.01,82.1) v1(123.01,82.1) v1(123.01,82.1) v1(123.11,66.9) v1(123.11,66.9) v1(123.11,66.9) v1(123.11,66.9) v1(123.19,1.01) v1(123.19,1.01) v1(123.28,64.84) v1(123.28,64.84) v1(123.28,64.84) v1(123.28,64.84) v1(123.35,24.8) v1(123.35,24.8) v1(123.41,80.9) v1(123.41,80.9) v1(123.41,80.9) v1(123.41,80.9) v1(123.41,9.5) v1(123.41,9.5) v1(123.64,49.53) v1(123.64,49.53) v1(123.64,47.56) v1(123.64,47.56) v1(124.04,13.87) v1(124.04,13.87) v1(124.34,43.13) v1(124.34,43.13) v1(124.41,82.9) v1(124.41,82.9) v1(124.41,45.5) v1(124.41,45.5) v1(124.56,33.95) v1(124.56,33.95) v1(124.59,74) v1(124.59,74) v1(124.59,74) v1(124.59,74) v1(124.59,74) v1(124.59,74) v1(124.69,78.74) v1(124.69,78.74) v1(124.69,78.74) v1(124.69,78.74) v1(124.69,78.74) v1(124.69,78.74) v1(124.81,30.91) v1(124.81,30.91) v1(124.81,30.91) v1(124.81,30.91) v1(125.19,5.37) v1(125.19,5.37) v1(125.31,82.8) v1(125.31,82.8) v1(125.62,89.97) v1(125.62,89.97) v1(125.6,77.96) v1(125.6,77.96) v1(125.6,77.96) v1(125.6,77.96) v1(125.6,77.96) v1(125.6,77.96) v1(125.64,76.33) v1(126.01,104.2) v1(126.01,104.2) v1(126.3,9.84) v1(126.3,9.84) v1(126.38,33.94) v1(126.38,33.94) v1(126.46,85.89) v1(126.46,85.89) v1(127.03,47.46) v1(127.03,47.46) v1(127.29,2.88) v1(127.29,2.88) v1(127.38,32.38) v1(127.38,32.38) v1(127.38,32.38) v1(127.38,32.38) v1(127.37,29.39) v1(127.37,29.39) v1(127.37,29.39) v1(127.37,29.39) v1(127.53,7.14) v1(127.53,7.14) v1(127.91,13.9) v1(127.91,13.9) v1(128.01,18.2) v1(128.01,18.2) v1(128.27,1.01) v1(128.27,1.01) v1(128.68,9.48) v1(128.68,9.48) v1(129.12,5.43) v1(129.12,5.43) v1(129.21,104.2) v1(129.21,104.2) v1(129.89,30.91) v1(129.89,30.91) v1(129.89,30.91) v1(129.89,30.91) v1(131.01,86.1) v1(131.01,86.1) v1(131.01,81.3) v1(131.01,81.3) v1(131.27,33.91) v1(131.27,33.91) v1(131.51,9.5) v1(131.51,9.5) v1(131.71,104.2) v1(131.71,104.2) v1(132.59,2.73) v1(132.59,2.73) v1(132.92,7.98) v1(132.92,7.98) v1(133.08,70.66) v1(133.08,70.66) v1(133.08,70.66) v1(133.08,70.66) v1(133.08,70.66) v1(133.08,70.66) v1(133.08,70.66) v1(133.35,1.01) v1(133.35,1.01) v1(133.38,48.01) v1(133.38,48.01) v1(133.38,48.01) v1(133.64,5.56) v1(133.64,5.56) v1(133.7,34.58) v1(133.7,34.58) v1(134.01,9.5) v1(134.01,9.5) v1(134.11,77.5) v1(134.11,77.5) v1(134.11,77.5) v1(134.11,77.5) v1(134.11,76.6) v1(134.11,76.6) v1(134.23,69.96) v1(134.23,69.96) v1(134.23,69.96) v1(134.23,69.96) v1(134.23,69.96) v1(134.23,69.96) v1(134.23,69.96) v1(134.41,93.6) v1(134.41,93.6) v1(134.41,93.6) v1(134.41,93.6) v1(134.36,72.66) v1(134.36,72.66) v1(134.36,72.66) v1(134.36,72.66) v1(134.36,72.66) v1(134.36,72.66) v1(134.36,72.66) v1(134.55,49.36) v1(134.55,49.36) v1(134.55,49.36) v1(134.71,15.9) v1(134.71,15.9) v1(134.79,36.94) v1(134.79,36.94) v1(135.73,35.98) v1(135.73,35.98) v1(135.71,21.8) v1(135.71,21.8) v1(135.9,30.89) v1(135.9,30.89) v1(136.08,83.43) v1(136.08,83.43) v1(136.08,83.43) v1(136.08,83.43) v1(136.54,58.35) v1(136.54,58.35) v1(136.51,55.5) v1(136.51,55.5) v1(136.61,104.2) v1(136.61,104.2) v1(136.6,34.04) v1(136.6,34.04) v1(136.91,21.7) v1(136.91,21.7) v1(136.91,21.7) v1(136.91,21.7) v1(137.01,84.9) v1(137.01,84.9) v1(137.06,35.12) v1(137.06,35.12) v1(137.21,52.92) v1(137.21,52.92) v1(137.25,18.44) v1(137.25,18.44) v1(137.54,92.29) v1(137.54,92.29) v1(137.54,92.29) v1(137.54,92.29) v1(137.55,60.08) v1(137.55,60.08) v1(137.55,60.08) v1(137.55,60.08) v1(137.55,60.08) v1(137.55,60.08) v1(137.56,61.13) v1(137.56,61.13) v1(137.56,61.13) v1(137.56,61.13) v1(137.56,61.13) v1(137.56,61.13) v1(137.56,59.12) v1(137.56,59.12) v1(137.56,59.12) v1(137.56,59.12) v1(137.57,58.13) v1(137.57,58.13) v1(137.57,58.13) v1(137.57,58.13) v1(137.59,55.05) v1(137.59,55.05) v1(137.59,55.05) v1(137.59,55.05) v1(138.02,47.24) v1(138.02,47.24) v1(138.01,10.7) v1(138.01,10.7) v1(137.96,8.45) v1(137.96,8.45) v1(138.31,92.3) v1(138.31,92.3) v1(138.31,92.3) v1(138.31,92.3) v1(138.35,38.29) v1(138.35,38.29) v1(138.43,1.01) v1(138.43,1.01) v1(138.52,40.94) v1(138.52,40.94) v1(138.81,81.3) v1(138.81,81.3) v1(138.81,81.3) v1(138.81,81.3) v1(138.81,80.6) v1(138.81,80.6) v1(138.81,80.6) v1(138.81,80.6) v1(138.81,47.1) v1(138.81,47.1) v1(139.02,52.04) v1(139.02,52.04) v1(139.56,92.32) v1(139.56,92.32) v1(139.56,92.32) v1(139.56,92.32) v1(140.03,53.21) v1(140.03,53.21) v1(140.19,62.03) v1(140.19,62.03) v1(140.27,48.59) v1(140.27,48.59) v1(140.38,92.31) v1(140.38,92.31) v1(140.38,92.31) v1(140.38,92.31) v1(141.01,98) v1(141.01,98) v1(140.97,79.08) v1(140.97,79.08) v1(140.97,79.08) v1(140.97,79.08) v1(140.97,6.09) v1(140.97,6.09) v1(141.33,65.49) v1(141.33,65.49) v1(141.33,65.49) v1(141.33,65.49) v1(141.3,38.69) v1(141.3,38.69) v1(141.47,91.22) v1(141.47,91.22) v1(141.47,91.22) v1(141.47,91.22) v1(141.48,62.29) v1(141.48,62.29) v1(141.48,62.29) v1(141.48,62.29) v1(141.51,21.9) v1(141.51,21.9) v1(141.51,21.9) v1(141.51,21.9) v1(141.7,103.67) v1(141.7,103.67) v1(141.7,85.89) v1(141.7,85.89) v1(141.7,2.07) v1(141.7,2.07) v1(142.25,40.99) v1(142.25,40.99) v1(142.27,52.32) v1(142.27,52.32) v1(142.35,47.21) v1(142.35,47.21) v1(142.33,8.28) v1(142.33,8.28) v1(142.51,96) v1(142.51,96) v1(142.56,89) v1(142.56,89) v1(142.51,50.1) v1(142.51,50.1) v1(143.51,1.01) v1(143.51,1.01) v1(143.82,63.91) v1(143.82,63.91) v1(143.82,63.91) v1(143.82,63.91) v1(144.24,93.51) v1(144.24,93.51) v1(144.24,85.89) v1(144.24,85.89) v1(144.24,35.09) v1(144.24,35.09) v1(144.24,30.01) v1(144.24,30.01) v1(144.43,77.97) v1(144.43,77.97) v1(144.43,77.97) v1(144.43,77.97) v1(144.87,10.82) v1(144.87,10.82) v1(145.14,82.7) v1(145.14,82.7) v1(145.14,82.7) v1(145.14,82.7) v1(145.15,78.75) v1(145.15,78.75) v1(145.15,78.75) v1(145.15,78.75) v1(145.18,83.6) v1(145.18,83.6) v1(145.18,83.6) v1(145.18,83.6) v1(145.18,79.6) v1(145.18,79.6) v1(145.18,79.6) v1(145.18,79.6) v1(145.49,81.58) v1(145.49,81.58) v1(145.49,81.58) v1(145.49,81.58) v1(145.52,80.65) v1(145.52,80.65) v1(145.52,80.65) v1(145.52,80.65) v1(145.61,44.4) v1(145.61,44.4) v1(145.74,23.84) v1(145.74,23.84) v1(145.74,23.84) v1(145.74,23.84) v1(146.78,90.97) v1(146.78,90.97) v1(146.78,85.89) v1(146.78,85.89) v1(146.78,83.35) v1(146.78,83.35) v1(146.78,80.81) v1(146.78,80.81) v1(146.78,78.27) v1(146.78,78.27) v1(146.78,37.63) v1(146.78,37.63) v1(146.78,32.55) v1(146.78,32.55) v1(146.78,27.47) v1(146.78,27.47) v1(147.41,13.36) v1(147.41,13.36) v1(148.11,103.5) v1(148.11,103.5) v1(148.11,1.4) v1(148.59,8.63) v1(148.59,8.63) v1(149.03,86.82) v1(149.03,86.82) v2(60.91,73.9) v2(60.91,73.9) v2(60.91,73.9) v2(60.91,73.9) v2(60.91,73.9) v2(60.91,73.9) v2(60.91,73.9) v2(97.11,17.6) v2(97.11,17.6) v2(97.11,17.6) v2(97.11,17.6) v2(97.11,17.6) v2(97.11,17.6) v2(97.11,17.6)
